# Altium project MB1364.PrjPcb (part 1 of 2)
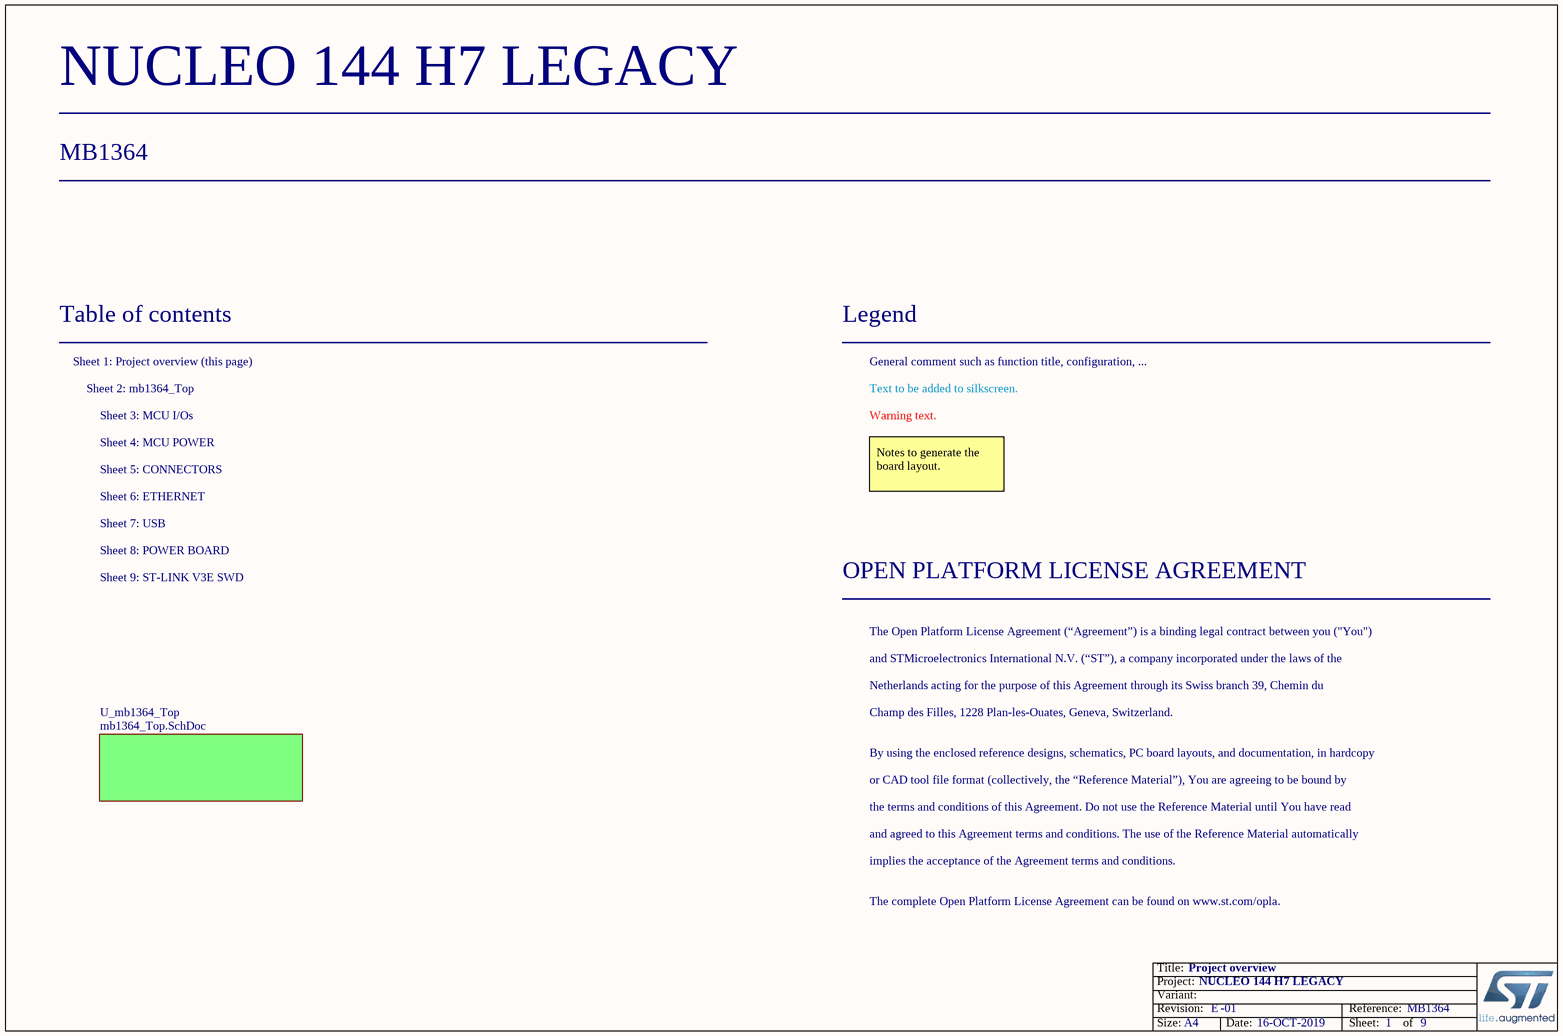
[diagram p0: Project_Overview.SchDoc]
Board_Reference: MB1364; Board_PCB_Revision: E; Board_Name: NUCLEO 144 H7 LEGACY; Board_Document_Date: 16-OCT-2019; Board_Assembly_Revision: 01
9 sheets, 324 parts. Net scope: flat (ports and power ports of the same name join across sheets).
Board file: MB1364.PcbDoc
Sheets:
  Project_Overview.SchDoc
    U_mb1364_Top = MB1364_Top.SchDoc
      U_Connectors = Connectors.SchDoc
      U_Power_Board = Power_Board.SchDoc
      U_MCU_144_IOs = MCU_144_IOs.SchDoc
      U_MCU_144_POWER = MCU_144_POWER.SchDoc
      U_USB = USB.SchDoc
      U_Ethernet = Ethernet.SchDoc
      U_ST_LINK_V3E = ST_LINK_V3E.SchDoc

## Sheet Project_Overview.SchDoc: Project overview
size A4; Date: Not used; ApprovedBy: Not used; CheckedBy: Not used; Author: Not used; CompanyName: STMicroelectronics; DrawnBy: Not used; Engineer: Not used; Organization: Not used; Address1: Not used; Address2: Not used; Address3: Not used; Address4: Not used; DocumentNumber: 1; Revision: Not used; SheetNumber: 1; SheetTotal: 9

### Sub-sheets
U_mb1364_Top = mb1364_Top.SchDoc: no entries

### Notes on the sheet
- Table of contents
- Sheet 1: Project overview (this page)
- Legend
- General comment such as function title, configuration, ...
- Sheet 2: mb1364_Top
- Sheet 4: MCU POWER
- Sheet 3: MCU I/Os
- Text to be added to silkscreen.
- Warning text.
- Sheet 6: ETHERNET
- Sheet 5: CONNECTORS
- Notes to generate the board layout.
- Sheet 9: ST-LINK V3E SWD
- Sheet 7: USB
- Sheet 8: POWER BOARD
- OPEN PLATFORM LICENSE AGREEMENT
- The Open Platform License Agreement (“Agreement”) is a binding legal contract between you ("You")
- and STMicroelectronics International N.V. (“ST”), a company incorporated under the laws of the
- Netherlands acting for the purpose of this Agreement through its Swiss branch 39, Chemin du
- Champ des Filles, 1228 Plan-les-Ouates, Geneva, Switzerland.
- By using the enclosed reference designs, schematics, PC board layouts, and documentation, in hardcopy
- or CAD tool file format (collectively, the “Reference Material”), You are agreeing to be bound by
- the terms and conditions of this Agreement. Do not use the Reference Material until You have read
- and agreed to this Agreement terms and conditions. The use of the Reference Material automatically
- implies the acceptance of the Agreement terms and conditions.
- The complete Open Platform License Agreement can be found on www.st.com/opla.

## Sheet MB1364_Top.SchDoc: MB1364 Top: hierarchical view
size A4; Date: Not used; ApprovedBy: Not used; CheckedBy: Not used; Author: Not used; CompanyName: STMicroelectronics; DrawnBy: Not used; Engineer: Not used; Organization: Not used; Address1: Not used; Address2: Not used; Address3: Not used; Address4: Not used; DocumentNumber: 2; Revision: Not used; SheetNumber: 2; SheetTotal: 9
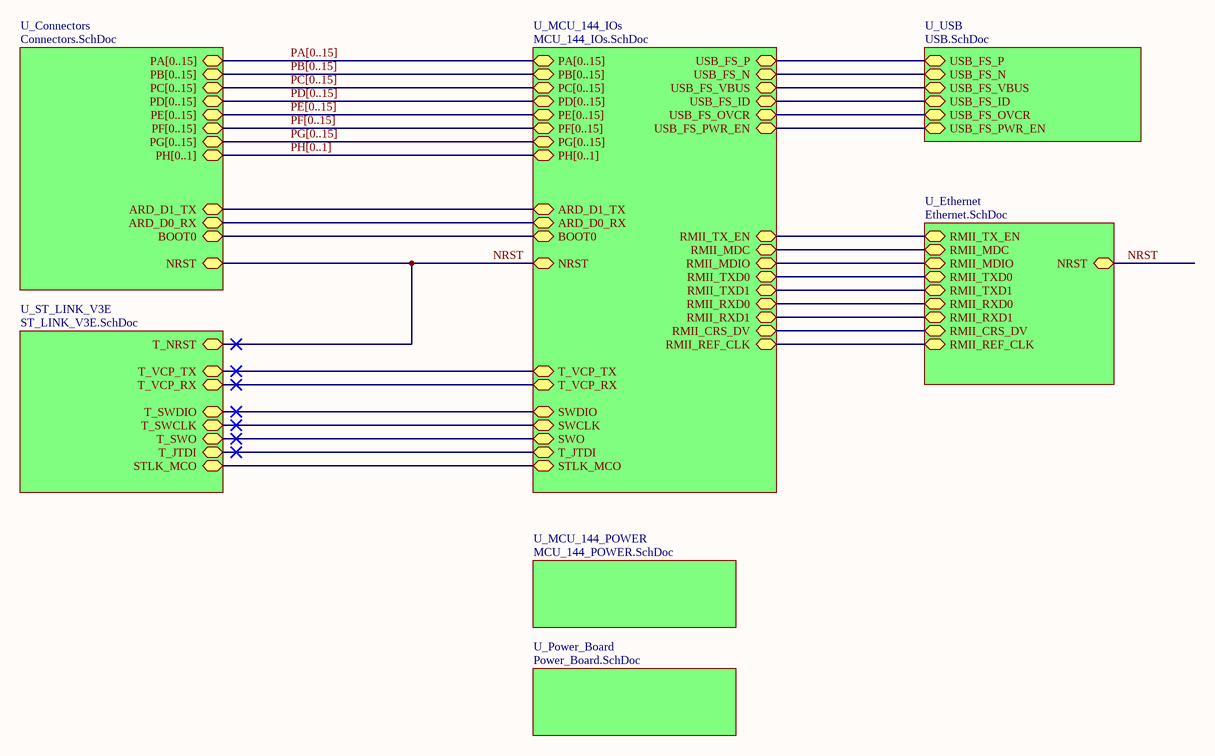
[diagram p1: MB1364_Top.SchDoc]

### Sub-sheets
U_Connectors = Connectors.SchDoc: PA[0..15] (bidir), PB[0..15] (bidir), PC[0..15] (bidir), PD[0..15] (bidir), PE[0..15] (bidir), PH[0..1] (bidir), ARD_D1_TX (bidir), ARD_D0_RX (bidir), NRST, BOOT0, PF[0..15] (bidir), PG[0..15] (bidir)
U_Ethernet = Ethernet.SchDoc: RMII_CRS_DV (bidir), RMII_REF_CLK (bidir), RMII_TXD0 (bidir), RMII_RXD0 (bidir), RMII_TX_EN (bidir), NRST (bidir), RMII_RXD1 (bidir), RMII_MDC (bidir), RMII_TXD1 (bidir), RMII_MDIO (bidir)
U_MCU_144_IOs = MCU_144_IOs.SchDoc: NRST (bidir), BOOT0 (bidir), SWO (bidir), STLK_MCO (bidir), SWCLK (bidir), SWDIO (bidir), RMII_TX_EN (bidir), RMII_MDC (bidir), RMII_TXD0 (bidir), RMII_TXD1 (bidir), RMII_REF_CLK (bidir), RMII_RXD1 (bidir), RMII_MDIO (bidir), RMII_CRS_DV (bidir), RMII_RXD0 (bidir), USB_FS_N (bidir), USB_FS_P (bidir), USB_FS_PWR_EN (bidir), USB_FS_VBUS (bidir), USB_FS_ID (bidir), T_VCP_TX (bidir), T_VCP_RX (bidir), PA[0..15] (bidir), PB[0..15] (bidir), PC[0..15] (bidir), PD[0..15] (bidir), PE[0..15] (bidir), PH[0..1] (bidir), ARD_D1_TX (bidir), ARD_D0_RX (bidir), USB_FS_OVCR, T_JTDI (bidir), PG[0..15] (bidir), PF[0..15] (bidir)
U_MCU_144_POWER = MCU_144_POWER.SchDoc: no entries
U_Power_Board = Power_Board.SchDoc: no entries
U_ST_LINK_V3E = ST_LINK_V3E.SchDoc: T_NRST (bidir), STLK_MCO (bidir), T_SWDIO (bidir), T_VCP_TX (bidir), T_VCP_RX (bidir), T_SWCLK (bidir), T_SWO (bidir), T_JTDI (bidir)
U_USB = USB.SchDoc: USB_FS_VBUS, USB_FS_N, USB_FS_P, USB_FS_ID, USB_FS_PWR_EN, USB_FS_OVCR

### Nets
NRST: sheet U_Connectors/NRST, sheet U_MCU_144_IOs/NRST, sheet U_Ethernet/NRST, sheet U_ST_LINK_V3E/T_NRST
(unnamed): sheet U_Connectors/ARD_D1_TX, sheet U_MCU_144_IOs/ARD_D1_TX
(unnamed): sheet U_Connectors/ARD_D0_RX, sheet U_MCU_144_IOs/ARD_D0_RX  [a separate net that carries the same name]
(unnamed): sheet U_Connectors/BOOT0, sheet U_MCU_144_IOs/BOOT0  [a separate net that carries the same name]
(unnamed): sheet U_MCU_144_IOs/SWO, sheet U_ST_LINK_V3E/T_SWO  [a separate net that carries the same name]
(unnamed): sheet U_MCU_144_IOs/STLK_MCO, sheet U_ST_LINK_V3E/STLK_MCO  [a separate net that carries the same name]
(unnamed): sheet U_MCU_144_IOs/SWCLK, sheet U_ST_LINK_V3E/T_SWCLK  [a separate net that carries the same name]
(unnamed): sheet U_MCU_144_IOs/SWDIO, sheet U_ST_LINK_V3E/T_SWDIO  [a separate net that carries the same name]
(unnamed): sheet U_MCU_144_IOs/RMII_TX_EN, sheet U_Ethernet/RMII_TX_EN  [a separate net that carries the same name]
(unnamed): sheet U_MCU_144_IOs/RMII_MDC, sheet U_Ethernet/RMII_MDC  [a separate net that carries the same name]
(unnamed): sheet U_MCU_144_IOs/RMII_TXD0, sheet U_Ethernet/RMII_TXD0  [a separate net that carries the same name]
(unnamed): sheet U_MCU_144_IOs/RMII_TXD1, sheet U_Ethernet/RMII_TXD1  [a separate net that carries the same name]
(unnamed): sheet U_MCU_144_IOs/RMII_REF_CLK, sheet U_Ethernet/RMII_REF_CLK  [a separate net that carries the same name]
(unnamed): sheet U_MCU_144_IOs/RMII_RXD1, sheet U_Ethernet/RMII_RXD1  [a separate net that carries the same name]
(unnamed): sheet U_MCU_144_IOs/RMII_MDIO, sheet U_Ethernet/RMII_MDIO  [a separate net that carries the same name]
(unnamed): sheet U_MCU_144_IOs/RMII_CRS_DV, sheet U_Ethernet/RMII_CRS_DV  [a separate net that carries the same name]
(unnamed): sheet U_MCU_144_IOs/RMII_RXD0, sheet U_Ethernet/RMII_RXD0  [a separate net that carries the same name]
(unnamed): sheet U_MCU_144_IOs/USB_FS_N, sheet U_USB/USB_FS_N  [a separate net that carries the same name]
(unnamed): sheet U_MCU_144_IOs/USB_FS_P, sheet U_USB/USB_FS_P  [a separate net that carries the same name]
(unnamed): sheet U_MCU_144_IOs/USB_FS_PWR_EN, sheet U_USB/USB_FS_PWR_EN  [a separate net that carries the same name]
(unnamed): sheet U_MCU_144_IOs/USB_FS_VBUS, sheet U_USB/USB_FS_VBUS  [a separate net that carries the same name]
(unnamed): sheet U_MCU_144_IOs/USB_FS_ID, sheet U_USB/USB_FS_ID  [a separate net that carries the same name]
(unnamed): sheet U_MCU_144_IOs/T_VCP_TX, sheet U_ST_LINK_V3E/T_VCP_TX  [a separate net that carries the same name]
(unnamed): sheet U_MCU_144_IOs/T_VCP_RX, sheet U_ST_LINK_V3E/T_VCP_RX  [a separate net that carries the same name]
(unnamed): sheet U_MCU_144_IOs/USB_FS_OVCR, sheet U_USB/USB_FS_OVCR  [a separate net that carries the same name]
(unnamed): sheet U_MCU_144_IOs/T_JTDI, sheet U_ST_LINK_V3E/T_JTDI  [a separate net that carries the same name]

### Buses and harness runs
bus PA[0..15] = sheet U_Connectors/PA[0..15] = sheet U_MCU_144_IOs/PA[0..15]
bus PB[0..15] = sheet U_Connectors/PB[0..15] = sheet U_MCU_144_IOs/PB[0..15]
bus PC[0..15] = sheet U_Connectors/PC[0..15] = sheet U_MCU_144_IOs/PC[0..15]
bus PD[0..15] = sheet U_Connectors/PD[0..15] = sheet U_MCU_144_IOs/PD[0..15]
bus PE[0..15] = sheet U_Connectors/PE[0..15] = sheet U_MCU_144_IOs/PE[0..15]
bus PF[0..15] = sheet U_Connectors/PF[0..15] = sheet U_MCU_144_IOs/PF[0..15]
bus PG[0..15] = sheet U_Connectors/PG[0..15] = sheet U_MCU_144_IOs/PG[0..15]
bus PH[0..1] = sheet U_Connectors/PH[0..1] = sheet U_MCU_144_IOs/PH[0..1]

## Sheet Connectors.SchDoc: Connectors
size A3; Date: Not used; ApprovedBy: Not used; CheckedBy: Not used; Author: Not used; CompanyName: STMicroelectronics; DrawnBy: Not used; Engineer: Not used; Organization: Not used; Address1: Not used; Address2: Not used; Address3: Not used; Address4: Not used; DocumentNumber: 5; Revision: Not used; SheetNumber: 5; SheetTotal: 9
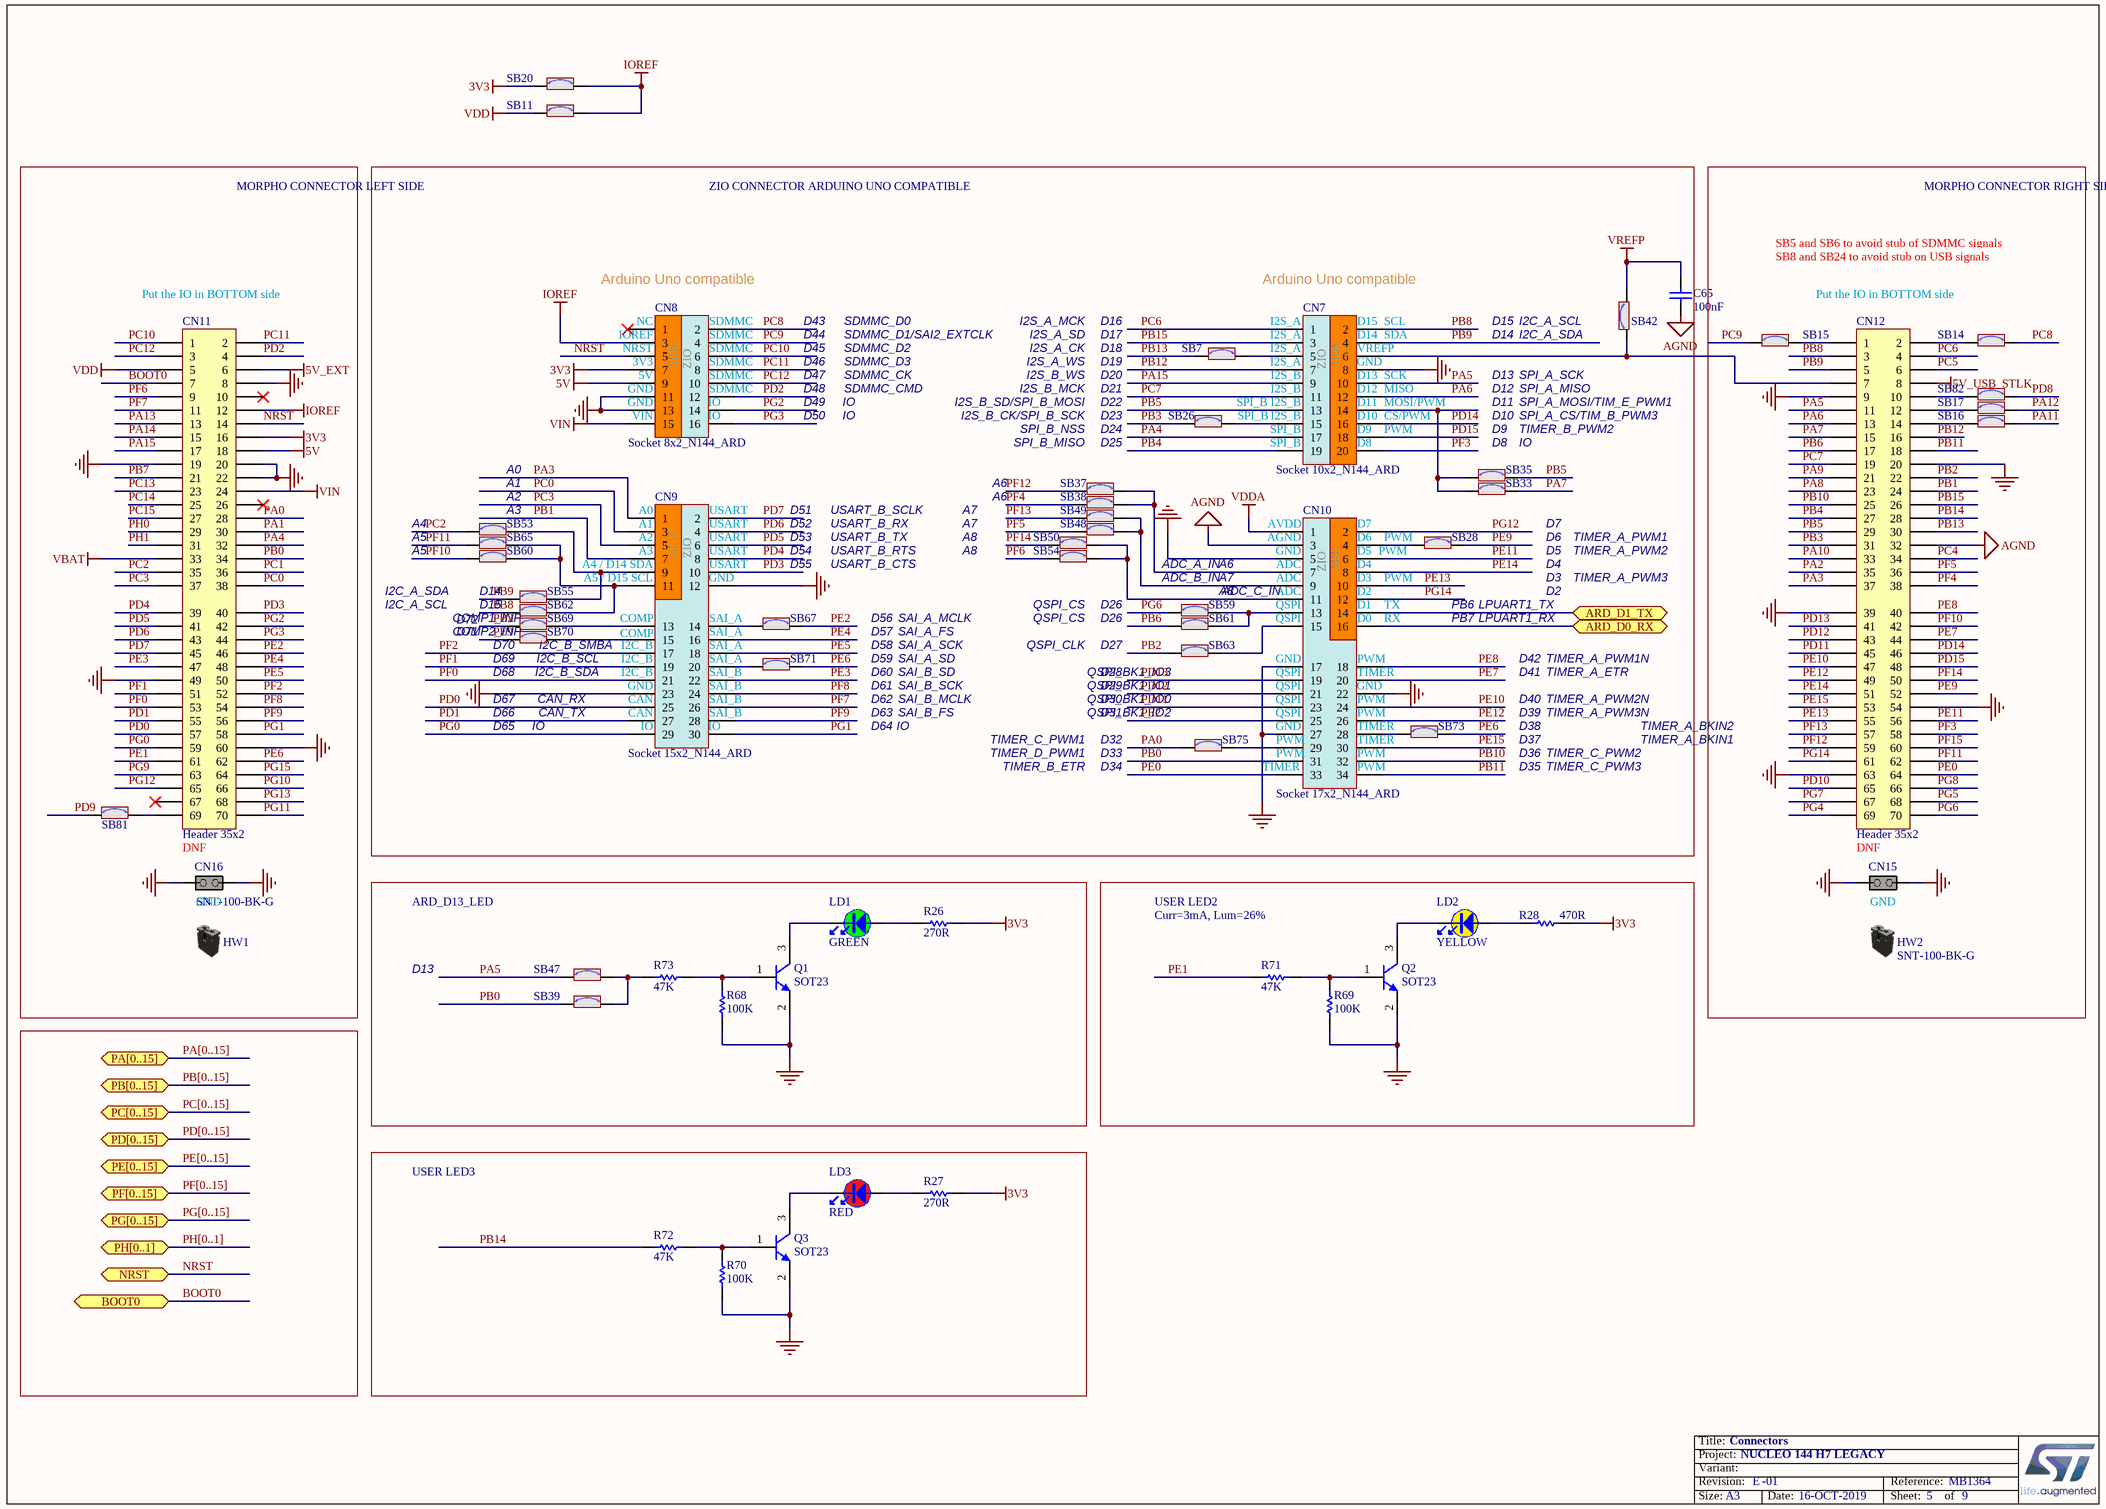
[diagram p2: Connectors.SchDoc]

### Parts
C65  value 100nF  [C0603]  (hidden comment: Capacitor)
CN7  Socket 10x2_N144_ARD  [CON_SAMTEC_SSW-110-23-X-D_N144_ARD]
CN8  Socket 8x2_N144_ARD  [CON_SAMTEC_SSW-108-23-X-D_N144_ARD]
CN9  Socket 15x2_N144_ARD  [CON_SAMTEC_SSW-115-23-X-D_N144_ARD]
CN10  Socket 17x2_N144_ARD  [CON_SAMTEC_SSW-117-23-X-D_N144_ARD]
CN11  Header 35x2  [CON_SAMTEC_TSW-135-07-X-D]
CN12  Header 35x2  [CON_SAMTEC_TSW-135-07-X-D]
CN15  Jumper_Header 2x1  [CON_SAMTEC_TSW-102-09-X-S]  (value not drawn)
CN16  Jumper_Header 2x1  [CON_SAMTEC_TSW-102-09-X-S]  (value not drawn)
HW1  value SNT-100-BK-G  (hidden comment: Shunt Black 2.54mm)  (mechanical)
HW2  value SNT-100-BK-G  (hidden comment: Shunt Black 2.54mm)  (mechanical)
LD1  value GREEN  [LED_0603_OSRAM_LG-Q396-PS-35_GREEN_1A2K_H0P4]  (hidden comment: LED_green)
LD2  value YELLOW  [LED_0603_OSRAM_LY-Q396-P1Q2-36_YELLOW_1A2K_H0P4]  (hidden comment: LED_yellow)
LD3  value RED  [LED_0603_OSRAM_LS-Q976-NR-1_RED_1A2K_H0P8]  (hidden comment: LED_red)
Q1  value SOT23  [NPN_SOT23]  (hidden comment: 9013-SOT23)
Q2  value SOT23  [NPN_SOT23]  (hidden comment: 9013-SOT23)
Q3  value SOT23  [NPN_SOT23]  (hidden comment: 9013-SOT23)
R26  value 270R  [R0402]  (hidden comment: Resistor)
R27  value 270R  [R0402]  (hidden comment: Resistor)
R28  value 470R  [R0402]  (hidden comment: Resistor)
R68  value 100K  [R0603]  (hidden comment: Resistor)
R69  value 100K  [R0603]  (hidden comment: Resistor)
R70  value 100K  [R0603]  (hidden comment: Resistor)
R71  value 47K  [R0603]  (hidden comment: Resistor)
R72  value 47K  [R0603]  (hidden comment: Resistor)
R73  value 47K  [R0603]  (hidden comment: Resistor)
SB7  SB_ON  [SOLDER-BRIDGE_R0603-0R]  (value not drawn)
SB11  SB_ON  [SOLDER-BRIDGE_R0603-0R]  (value not drawn)
SB14  SB_ON  [SOLDER-BRIDGE_R0603-0R]  (value not drawn)
SB15  SB_ON  [SOLDER-BRIDGE_R0603-0R]  (value not drawn)
SB16  SB_ON  [SOLDER-BRIDGE_R0603-0R]  (value not drawn)
SB17  SB_ON  [SOLDER-BRIDGE_R0603-0R]  (value not drawn)
SB20  SB_ON  [SOLDER-BRIDGE_R0603-0R]  (value not drawn)
SB26  SB_ON  [SOLDER-BRIDGE_R0603-0R]  (value not drawn)
SB28  SB_ON  [SOLDER-BRIDGE_R0402-0R]  (value not drawn)
SB33  SB_ON  [SOLDER-BRIDGE_R0603-0R]  (value not drawn)
SB35  SB_ON  [SOLDER-BRIDGE_R0603-0R]  (value not drawn)
SB37  SB_ON  [SOLDER-BRIDGE_R0402-0R]  (value not drawn)
SB38  SB_ON  [SOLDER-BRIDGE_R0402-0R]  (value not drawn)
SB39  SB_ON  [SOLDER-BRIDGE_R0603-0R]  (value not drawn)
SB42  SB_ON  [SOLDER-BRIDGE_R0603-0R]  (value not drawn)
SB47  SB_ON  [SOLDER-BRIDGE_R0603-0R]  (value not drawn)
SB48  SB_ON  [SOLDER-BRIDGE_R0402-0R]  (value not drawn)
SB49  SB_ON  [SOLDER-BRIDGE_R0402-0R]  (value not drawn)
SB50  SB_ON  [SOLDER-BRIDGE_R0402-0R]  (value not drawn)
SB53  SB_ON  [SOLDER-BRIDGE_R0402-0R]  (value not drawn)
SB54  SB_ON  [SOLDER-BRIDGE_R0402-0R]  (value not drawn)
SB55  SB_ON  [SOLDER-BRIDGE_R0402-0R]  (value not drawn)
SB59  SB_ON  [SOLDER-BRIDGE_R0402-0R]  (value not drawn)
SB60  SB_ON  [SOLDER-BRIDGE_R0402-0R]  (value not drawn)
SB61  SB_ON  [SOLDER-BRIDGE_R0402-0R]  (value not drawn)
SB62  SB_ON  [SOLDER-BRIDGE_R0402-0R]  (value not drawn)
SB63  SB_ON  [SOLDER-BRIDGE_R0402-0R]  (value not drawn)
SB65  SB_ON  [SOLDER-BRIDGE_R0402-0R]  (value not drawn)
SB67  SB_ON  [SOLDER-BRIDGE_R0402-0R]  (value not drawn)
SB69  SB_ON  [SOLDER-BRIDGE_R0402-0R]  (value not drawn)
SB70  SB_ON  [SOLDER-BRIDGE_R0402-0R]  (value not drawn)
SB71  SB_ON  [SOLDER-BRIDGE_R0402-0R]  (value not drawn)
SB73  SB_ON  [SOLDER-BRIDGE_R0402-0R]  (value not drawn)
SB75  SB_ON  [SOLDER-BRIDGE_R0402-0R]  (value not drawn)
SB81  SB_ON  [SOLDER-BRIDGE_R0402-0R]  (value not drawn)
SB82  SB_ON  [SOLDER-BRIDGE_R0402-0R]  (value not drawn)

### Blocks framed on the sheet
USER LED3: LD3 Q3 R27 R70 R72

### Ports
ARD_D0_RX (bidir), ARD_D1_TX (bidir), BOOT0, NRST, PA[0..15] (bidir), PB[0..15] (bidir), PC[0..15] (bidir), PD[0..15] (bidir), PE[0..15] (bidir), PF[0..15] (bidir), PG[0..15] (bidir), PH[0..1] (bidir)

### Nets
3V3: CN8.7 CN11.16 R26.2 R27.2 R28.2 SB20.1
5V: CN8.9 CN11.18
5V_EXT: CN11.6
5V_USB_STLK: CN12.8
AGND: C65.1 CN10.3 CN12.32
GND: CN7.8 CN8.11 CN8.13 CN9.12 CN9.23 CN10.5 CN10.17 CN10.22 CN10.27 CN11.8 CN11.19 CN11.20 CN11.22 CN11.49 CN11.60 CN12.9 CN12.20 CN12.39 CN12.54 CN12.63 CN15.1(COMMON) CN15.2(NO) CN16.1(COMMON) CN16.2(NO) Q1.2(E) Q2.2(E) Q3.2(E) R68.1 R69.1 R70.1
IOREF: CN8.3 CN11.12 SB11.2 SB20.2
VBAT: CN11.33
VDD: CN11.5 SB11.1
VDDA: CN10.1
VIN: CN8.15 CN11.24
VREFP: C65.2 SB42.2
ARD_D0_RX: CN10.16 ; port ARD_D0_RX
ARD_D1_TX: CN10.14 ; port ARD_D1_TX
BOOT0: CN11.7 ; port BOOT0
NRST: CN8.5 CN11.14 ; port NRST
PA0: CN11.28 SB75.1
PA1: CN11.30
PA2: CN12.35
PA3: CN9.1 CN12.37
PA4: CN7.17 CN11.32
PA5: CN7.10 CN12.11 SB47.1
PA6: CN7.12 CN12.13
PA7: CN12.15 SB33.2
PA8: CN12.23
PA9: CN12.21
PA10: CN12.33
PA11: SB16.2
PA12: SB17.2
PA13: CN11.13
PA14: CN11.15
PA15: CN7.9 CN11.17
PB0: CN10.31 CN11.34 SB39.1
PB1: CN9.7 CN12.24
PB2: CN12.22 SB63.1 SB69.1
PB3: CN12.31 SB26.1
PB4: CN7.19 CN12.27
PB5: CN7.13 CN12.29 SB35.2
PB6: CN12.17 SB61.1
PB7: CN11.21
PB8: CN7.2 CN12.3 SB62.1
PB9: CN7.4 CN12.5 SB55.1
PB10: CN10.32 CN12.25
PB11: CN10.34 CN12.18
PB12: CN7.7 CN12.16
PB13: CN12.30 SB7.1
PB14: CN12.28 R72.1
PB15: CN7.3 CN12.26
PC0: CN9.3 CN11.38
PC1: CN11.36
PC2: CN11.35 SB53.1
PC3: CN9.5 CN11.37
PC4: CN12.34
PC5: CN12.6
PC6: CN7.1 CN12.4
PC7: CN7.11 CN12.19
PC8: CN8.2 SB14.2
PC9: CN8.4 SB15.1
PC10: CN8.6 CN11.1
PC11: CN8.8 CN11.2
PC12: CN8.10 CN11.3
PC13: CN11.23
PC14: CN11.25
PC15: CN11.27
PD0: CN9.25 CN11.57
PD1: CN9.27 CN11.55
PD2: CN8.12 CN11.4
PD3: CN9.10 CN11.40
PD4: CN9.8 CN11.39
PD5: CN9.6 CN11.41
PD6: CN9.4 CN11.43
PD7: CN9.2 CN11.45
PD8: SB82.2
PD9: SB81.1
PD10: CN12.65
PD11: CN10.23 CN12.45
PD12: CN10.21 CN12.43
PD13: CN10.19 CN12.41
PD14: CN7.16 CN12.46
PD15: CN7.18 CN12.48
PE0: CN10.33 CN12.64
PE1: CN11.61 R71.1
PE2: CN10.25 CN11.46 SB67.2
PE3: CN9.22 CN11.47
PE4: CN9.16 CN11.48
PE5: CN9.18 CN11.50
PE6: CN11.62 SB71.2 SB73.2
PE7: CN10.20 CN12.44
PE8: CN10.18 CN12.40
PE9: CN12.52 SB28.2 SB70.1
PE10: CN10.24 CN12.47
PE11: CN10.6 CN12.56
PE12: CN10.26 CN12.49
PE13: CN10.10 CN12.55
PE14: CN10.8 CN12.51
PE15: CN10.30 CN12.53
PF0: CN9.21 CN11.53
PF1: CN9.19 CN11.51
PF2: CN9.17 CN11.52
PF3: CN7.20 CN12.58
PF4: CN12.38 SB38.1
PF5: CN12.36 SB48.1
PF6: CN11.9 SB54.1
PF7: CN9.26 CN11.11
PF8: CN9.24 CN11.54
PF9: CN9.28 CN11.56
PF10: CN12.42 SB60.1
PF11: CN12.62 SB65.1
PF12: CN12.59 SB37.1
PF13: CN12.57 SB49.1
PF14: CN12.50 SB50.1
PF15: CN12.60
PG0: CN9.29 CN11.59
PG1: CN9.30 CN11.58
PG2: CN8.14 CN11.42
PG3: CN8.16 CN11.44
PG4: CN12.69
PG5: CN12.68
PG6: CN12.70 SB59.1
PG7: CN12.67
PG8: CN12.66
PG9: CN11.63
PG10: CN11.66
PG11: CN11.70
PG12: CN10.2 CN11.65
PG13: CN11.68
PG14: CN10.12 CN12.61
PG15: CN11.64
PH0: CN11.29
PH1: CN11.31
NetCN7_5: CN7.5 SB7.2
NetCN7_6: CN7.6 CN12.7 SB42.1
NetCN7_14: CN7.14 SB33.1 SB35.1
NetCN7_15: CN7.15 SB26.2
NetCN9_9: CN9.9 SB53.2 SB55.2
NetCN9_11: CN9.11 SB60.2 SB62.2 SB65.2
NetCN9_13: CN9.13 SB69.2
NetCN9_14: CN9.14 SB67.1
NetCN9_15: CN9.15 SB70.2
NetCN9_20: CN9.20 SB71.1
NetCN10_4: CN10.4 SB28.1
NetCN10_7: CN10.7 SB37.2 SB38.2
NetCN10_9: CN10.9 SB48.2 SB49.2
NetCN10_11: CN10.11 SB50.2 SB54.2
NetCN10_13: CN10.13 SB59.2 SB61.2
NetCN10_15: CN10.15 SB63.2
NetCN10_28: CN10.28 SB73.1
NetCN10_29: CN10.29 SB75.2
NetCN11_69: CN11.69 SB81.2
NetCN12_1: CN12.1 SB15.2
NetCN12_2: CN12.2 SB14.1
NetCN12_10: CN12.10 SB82.1
NetCN12_12: CN12.12 SB17.1
NetCN12_14: CN12.14 SB16.1
NetLD1_1: LD1.1 R26.1
NetLD1_2: LD1.2 Q1.3(C)
NetLD2_1: LD2.1 R28.1
NetLD2_2: LD2.2 Q2.3(C)
NetLD3_1: LD3.1 R27.1
NetLD3_2: LD3.2 Q3.3(C)
NetQ1_1: Q1.1(B) R68.2 R73.2
NetQ2_1: Q2.1(B) R69.2 R71.2
NetQ3_1: Q3.1(B) R70.2 R72.2
NetR73_1: R73.1 SB39.2 SB47.2

Not connected (* = marked no-connect by the designer): CN8 1*; CN11 10* 26* 67*

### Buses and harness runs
bus PA[0..15] = port PA[0..15]
bus PB[0..15] = port PB[0..15]
bus PC[0..15] = port PC[0..15]
bus PD[0..15] = port PD[0..15]
bus PE[0..15] = port PE[0..15]
bus PF[0..15] = port PF[0..15]
bus PG[0..15] = port PG[0..15]
bus PH[0..1] = port PH[0..1]

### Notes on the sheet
- MORPHO CONNECTOR LEFT SIDE
- ZIO CONNECTOR ARDUINO UNO COMPATIBLE
- MORPHO CONNECTOR RIGHT SIDE
- (near CN11) Put the IO in BOTTOM side
- (near CN8) Arduino Uno compatible
- (near CN7) Arduino Uno compatible
- SB5 and SB6 to avoid stub of SDMMC signals
- SB8 and SB24 to avoid stub on USB signals
- Put the IO in BOTTOM side
- (near CN8) NC
- (near CN8) IOREF
- (near CN8) NRST
- (near CN8) 3V3
- (near CN8) 5V
- (near CN8) SDMMC
- D43
- D44
- D45
- D46
- D47
- SDMMC_CK
- SDMMC_D0
- SDMMC_D1/SAI2_EXTCLK
- SDMMC_D2
- SDMMC_D3
- I2S_A_SD
- I2S_A_CK
- I2S_A_WS
- I2S_A_MCK
- I2S_B_WS
- D16
- D17
- D18
- D19
- D20
- (near CN7) I2S_A
- (near CN7) I2S_B
- (near CN7) VREFP
- (near CN7) D13
- (near CN7) D14
- (near CN7) D15
- (near CN7) SCL
- (near CN7) SDA
- (near CN7) SCK
- (near CN7) GND
- D15
- D14
- D13
- SPI_A_SCK
- (near SB42) I2C_A_SCL
- (near SB42) I2C_A_SDA
- (near CN8) GND
- (near CN8) VIN
- (near CN8) IO
- D48
- D49
- D50
- SDMMC_CMD
- IO
- I2S_B_SD/SPI_B_MOSI
- I2S_B_CK/SPI_B_SCK
- I2S_B_MCK
- SPI_B_MISO
- SPI_B_NSS
- D21
- D22
- D23
- D24
- D25
- SPI_B
- (near SB26) SPI_B
- (near CN7) SPI_B
- (near CN7) D8
- (near CN7) D9
- (near CN7) D10
- (near CN7) D11
- (near CN7) D12
- (near CN7) MISO
- (near CN7) MOSI/PWM
- (near CN7) CS/PWM
- (near CN7) PWM
- D12
- D11
- D10
- D9
- D8
- TIMER_B_PWM2
- SPI_A_CS/TIM_B_PWM3
- SPI_A_MOSI/TIM_E_PWM1
- SPI_A_MISO
- A0
- A1
- A2
- (near SB53) A3
- (near CN9) A0
- (near CN9) USART
- D51
- USART_B_SCLK
- A7
- A6
- A4
- A5
- (near CN9) A1
- (near CN9) A2
- (near CN9) A3
- (near CN9) A4 / D14 SDA
- (near CN9) A5 / D15 SCL
- (near CN9) GND
- D52
- D53
- D54
- D55
- USART_B_TX
- USART_B_RX
- USART_B_CTS
- USART_B_RTS
- A8
- ADC_A_IN
- ADC_B_IN
- (near CN10) GND
- (near CN10) AVDD
- (near CN10) AGND
- (near CN10) ADC
- (near CN10) D7
- (near CN10) D6
- (near CN10) D5
- (near CN10) D4
- (near CN10) D3
- PWM
- D5
- D6
- D7
- D4
- D3
- TIMER_A_PWM1
- TIMER_A_PWM2
- TIMER_A_PWM3
- I2C_A_SCL
- I2C_A_SDA
- COMP1_INP
- COMP2_INP
- D72
- D71
- D70
- (near SB70) I2C_B_SMBA
- (near CN9) COMP
- (near CN9) I2C_B
- (near CN9) SAI_A
- D56
- D57
- D58
- SAI_A_SCK
- SAI_A_FS
- SAI_A_MCLK
- QSPI_CLK
- QSPI_CS
- D26
- D27
- (near SB59) ADC_C_IN
- (near CN10) QSPI
- (near CN10) D2
- (near CN10) D1
- (near CN10) D0
- (near CN10) TX
- (near CN10) RX
- PB6
- PB7
- LPUART1_TX
- LPUART1_RX
- D2
- (near SB70) D69
- D68
- D67
- D66
- CAN_TX
- CAN_RX
- (near SB70) I2C_B_SCL
- I2C_B_SDA
- (near CN9) CAN
- (near CN9) SAI_B
- D59
- D60
- D61
- D62
- D63
- SAI_A_SD
- SAI_B_SD
- SAI_B_SCK
- SAI_B_FS
- SAI_B_MCLK
- QSPI_BK1_IO0
- QSPI_BK1_IO2
- QSPI_BK1_IO1
- QSPI_BK1_IO3
- D28
- D29
- D30
- D31
- (near CN10) TIMER
- (near CN10) PWM
- D39
- D40
- D41
- D42
- TIMER_A_PWM1N
- TIMER_A_PWM2N
- TIMER_A_PWM3N
- TIMER_A_ETR
- D65
- (near CN9) IO
- D64
- TIMER_D_PWM1
- TIMER_B_ETR
- TIMER_C_PWM1
- D32
- D33
- D34
- D35
- D36
- D37
- D38
- TIMER_C_PWM2
- TIMER_C_PWM3
- TIMER_A_BKIN1
- TIMER_A_BKIN2
- DNF
- GND
- ARD_D13_LED
- USER LED2
- Curr=3mA, Lum=26%

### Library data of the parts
C65 = MCD-00237: Capacitor, MLCC, 100nF, 6V3, X5R, 10%, 0603, T=0,8mm; Manufacturer_Part_Number: CC0603KRX5R5BB104; Manufacturer: YAGEO; Provided_By: SUBCO; ECCN_US: EAR99; ECCN_EU: NEC
CN7 = MCD-01039: Socket, 10x2, 2.54mm, VR, TH, Height 8.51mm/10mm, Low insertion force.; Part_Type: Connector; Manufacturer_Part_Number: SSW-110-23-x-D; Manufacturer: SAMTEC; Provided_By: SUBCO
CN8 = MCD-01037: Socket, 8x2, 2.54mm, VR, TH, Height 8.51mm/10mm, Low insertion force.; Part_Type: Connector; Manufacturer_Part_Number: SSW-108-23-x-D; Manufacturer: SAMTEC; Provided_By: SUBCO
CN9 = MCD-01040: Socket, 15x2, 2.54mm, VR, TH, Height 8.51mm/10mm, Low insertion force.; Part_Type: Connector; Manufacturer_Part_Number: SSW-115-23-x-D; Manufacturer: SAMTEC; Provided_By: SUBCO
CN10 = MCD-01041: Socket, 17x2, 2.54mm, VR, TH, Height 8.51mm/10mm, Low insertion force; Part_Type: Connector; Manufacturer_Part_Number: SSW-117-23-x-D; Manufacturer: SAMTEC; Provided_By: SUBCO
CN11 CN12 = MCD-01210: Header, 35x2, 2,54mm, VR, TH, Height 5.84mm/2.54mm; Part_Type: Connector; Manufacturer_Part_Number: TSW-135-07-x-D; Manufacturer: SAMTEC; Provided_By: SUBCO
CN15 CN16 = MCD-00214: Header, 2x1, 2,54mm, VR, TH, Height 5.84mm/10.16mm; Manufacturer_Part_Number: TSW-102-09-x-S; Manufacturer: SAMTEC; Part_Type: Connector; Value: Header 2x1 16mm; Provided_By: SUBCO
HW1 HW2 = MCD-00043: SHUNT 2.54mm BLACK; Manufacturer: SAMTEC; Part_Type: Mechanical; Alternate_Manufacturer_Part_Number: 316102S111A; Alternate_Manufacturer: JIUBABA; Provided_By: SUBCO
LD1 = MCD-00588: LED Green, 0603 SMD, Forward Voltage Typ=2V, Max=2.5V; Part_Type: Display; Manufacturer_Part_Number: LG Q396-PS-35; Manufacturer: OSRAM OPTO SEMICONDUCTORS; Alternate_Manufacturer_Part_Number: VLMTG1300-GS08; Alternate_Manufacturer: VISHAY SEMICONDUCTOR OPTO DIVISION; Provided_By: SUBCO
LD2 = MCD-01061: LED Yellow, 0603 SMD, Forward Voltage min=1.7V, Typ=2V, Max=2.3V; Part_Type: Display; Manufacturer_Part_Number: LY Q396-P1Q2-36; Manufacturer: OSRAM OPTO SEMICONDUCTORS; Provided_By: SUBCO
LD3 = MCD-00586: LED Red, 0603 SMD, Forward Voltage Typ=2V, Max=2.5V; Part_Type: Display; Manufacturer_Part_Number: LS Q976-NR-1; Manufacturer: OSRAM OPTO SEMICONDUCTORS; Alternate_Manufacturer_Part_Number: VLMS1300-GS08; Alternate_Manufacturer: VISHAY SEMICONDUCTOR OPTO DIVISION; Provided_By: SUBCO
Q1-Q3 = MCD-00073: NPN Bipolar Transistor; Part_Type: IC; Manufacturer_Part_Number: BSR14; Manufacturer: ON SEMICONDUCTOR; Alternate_Manufacturer_Part_Number: MMBT2222ALT1G / MMBT2222ALT3G; Provided_By: SUBCO; ECCN_US: EAR99; ECCN_EU: NEC
R26 R27 = MCD-00441: Resistor,270R,0402,1%,1/16W; Manufacturer_Part_Number: RC0402FR-07270RL; Manufacturer: YAGEO; Provided_By: SUBCO; ECCN_US: EAR99; ECCN_EU: NEC
R28 = MCD-00178: Resistor,470R,0402,1%,1/16W; Manufacturer_Part_Number: RC0402FR-07470RL; Manufacturer: YAGEO; Provided_By: SUBCO; ECCN_US: EAR99; ECCN_EU: NEC
R68-R70 = MCD-00223: Resistor,100K,0603,1%,1/10W; Manufacturer_Part_Number: RC0603FR-07100KL; Manufacturer: YAGEO; Provided_By: SUBCO; ECCN_US: EAR99; ECCN_EU: NEC
R71-R73 = MCD-00222: Resistor,47K,0603,1%,1/10W; Manufacturer_Part_Number: RC0603FR-0747KL; Manufacturer: YAGEO; Provided_By: SUBCO; ECCN_US: EAR99; ECCN_EU: NEC
SB7 SB11 SB14-SB17 SB20 SB26 SB33 SB35 SB39 SB42 SB47 = MCD-00071: Solder Bridge ON; Part_Type: Mechanical; Manufacturer_Part_Number: RC0603JR-070RL; Manufacturer: YAGEO; Provided_By: SUBCO
SB28 SB37 SB38 SB48-SB50 SB53-SB55 SB59-SB63 SB65 SB67 SB69-SB71 SB73 SB75 SB81 SB82 = MCD-01618: Solder Bridge 0402 ON; Part_Type: Mechanical; Manufacturer_Part_Number: RC0402JR-070RL; Manufacturer: YAGEO; Provided_By: SUBCO

## Sheet Power_Board.SchDoc: MAIN POWER 5V / 3V3 / 1V8
size A4; Date: Not used; ApprovedBy: Not used; CheckedBy: Not used; Author: Not used; CompanyName: STMicroelectronics; DrawnBy: Not used; Engineer: Not used; Organization: Not used; Address1: Not used; Address2: Not used; Address3: Not used; Address4: Not used; DocumentNumber: 9; Revision: Not used; SheetNumber: 8; SheetTotal: 9
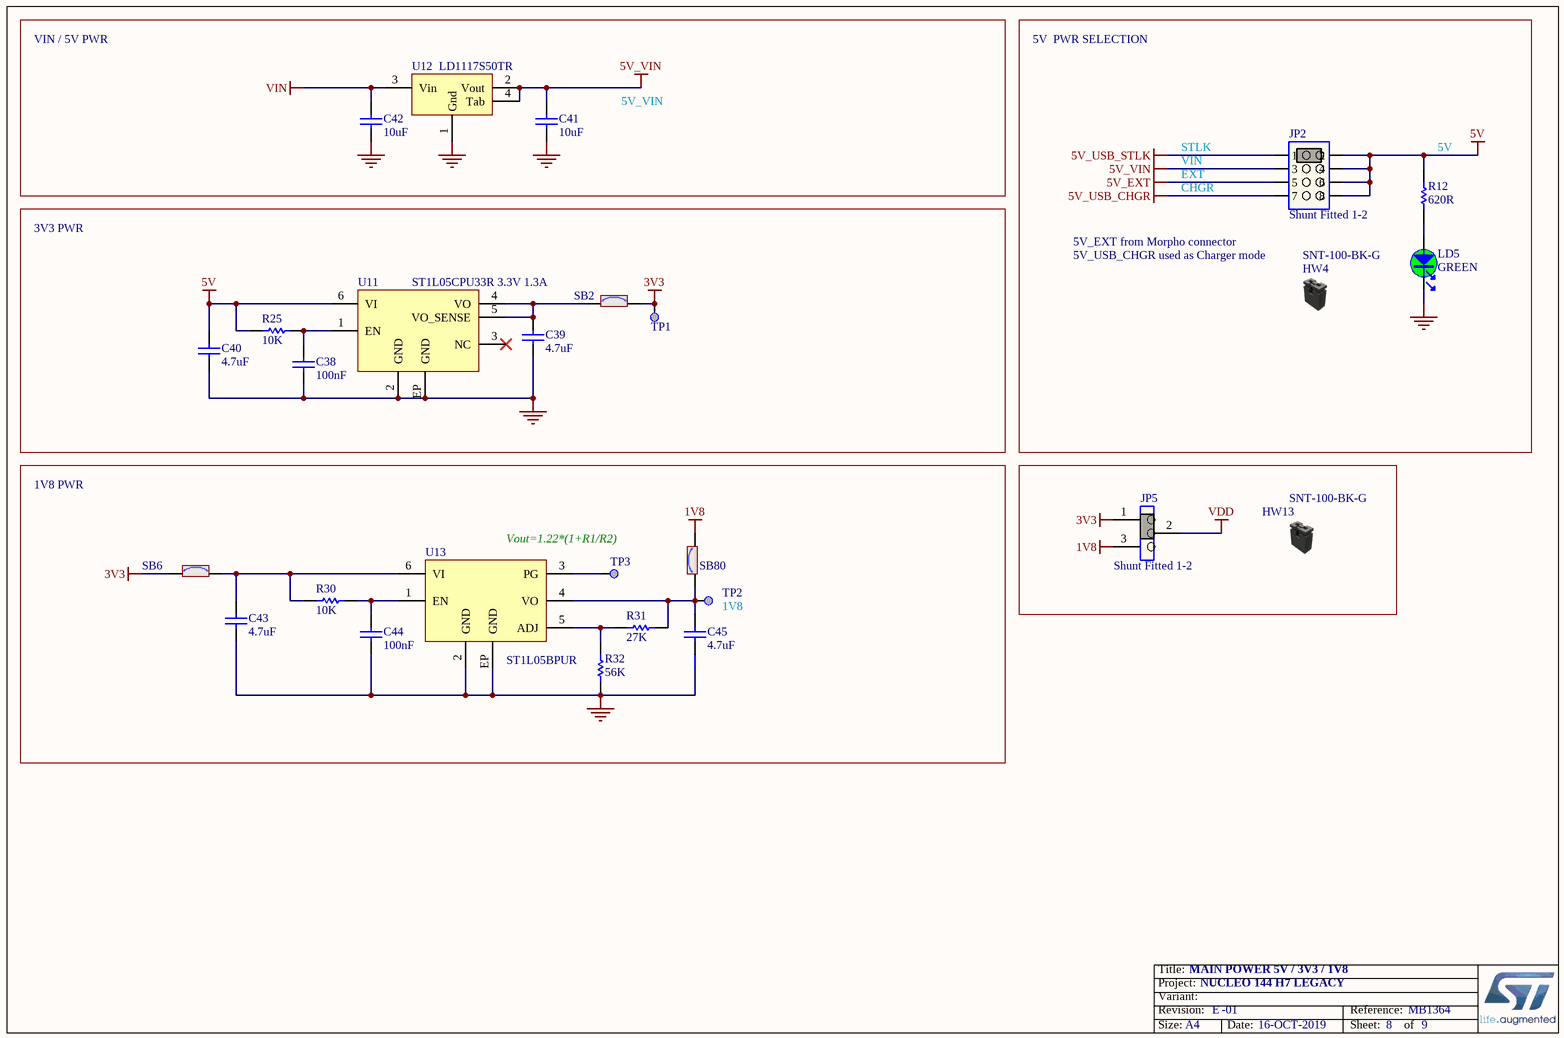
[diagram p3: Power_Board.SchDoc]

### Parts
C38  value 100nF  [C0402]  (hidden comment: Capacitor)
C39  value 4.7uF  [C0603]  (hidden comment: Capacitor)
C40  value 4.7uF  [C0603]  (hidden comment: Capacitor)
C41  value 10uF  [C0805]  (hidden comment: Capacitor)
C42  value 10uF  [C0805]  (hidden comment: Capacitor)
C43  value 4.7uF  [C0603]  (hidden comment: Capacitor)
C44  value 100nF  [C0603]  (hidden comment: Capacitor)
C45  value 4.7uF  [C0603]  (hidden comment: Capacitor)
HW4  value SNT-100-BK-G  (hidden comment: Shunt Black 2.54mm)  (mechanical)
HW13  value SNT-100-BK-G  (hidden comment: Shunt Black 2.54mm)  (mechanical)
JP2  value Shunt Fitted 1-2  [CON_SAMTEC_TSW-104-07-X-D]  (hidden comment: Jumper_Header 4x2 Fitted 1-2)
JP5  value Shunt Fitted 1-2  [CON_SAMTEC_TSW-103-07-F-S]  (hidden comment: Jumper_Header 3x1 Fitted 1-2)
LD5  value GREEN  [LED_0603_OSRAM_LG-Q396-PS-35_GREEN_1A2K_H0P4]  (hidden comment: LED_green)
R12  value 620R  [R0603]  (hidden comment: Resistor)
R25  value 10K  [R0402]  (hidden comment: Resistor)
R30  value 10K  [R0402]  (hidden comment: Resistor)
R31  value 27K  [R0402]  (hidden comment: Resistor)
R32  value 56K  [R0402]  (hidden comment: Resistor)
SB2  SB_ON  [SOLDER-BRIDGE_R0603-0R]  (value not drawn)
SB6  SB_ON  [SOLDER-BRIDGE_R0603-0R]  (value not drawn)
SB80  SB_ON  [SOLDER-BRIDGE_R0603-0R]  (value not drawn)
TP1  Test Point  [TP_SMD_1MM]  (value not drawn)  (no BOM)
TP2  Test Point  [TP_SMD_1MM]  (value not drawn)  (no BOM)
TP3  Test Point  [TP_SMD_1MM]  (value not drawn)  (no BOM)
U11  value ST1L05CPU33R 3.3V 1.3A  [ICC_DFN6-EPAD_3X3_P095]  (hidden comment: ST1L05CPU33R)
U12  LD1117S50TR  [REG_SOT223-TAB]
U13  ST1L05BPUR  [ICC_DFN6-EPAD_3X3_P095]

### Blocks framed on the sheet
3V3 PWR: C38-C40 R25 SB2 TP1 U11

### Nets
1V8: JP5.3 SB80.2
3V3: JP5.1 SB2.2 SB6.1 TP1.1
5V: C40.2 JP2.2 JP2.4 JP2.6 JP2.8 R12.2 R25.2 U11.6(VI)
5V_EXT: JP2.5
5V_USB_CHGR: JP2.7
5V_USB_STLK: JP2.1
5V_VIN: C41.2 JP2.3 U12.2(Vout) U12.4(Tab)
GND: C38.2 C39.1 C40.1 C41.1 C42.1 C43.1 C44.1 C45.1 LD5.2 R32.1 U11.2(GND) U11.EP(GND) U12.1(Gnd) U13.2(GND) U13.EP(GND)
VDD: JP5.2
VIN: C42.2 U12.3(Vin)
NetC38_1: C38.1 R25.1 U11.1(EN)
NetC39_2: C39.2 SB2.1 U11.4(VO) U11.5(VO_SENSE)
NetC43_2: C43.2 R30.2 SB6.2 U13.6(VI)
NetC44_2: C44.2 R30.1 U13.1(EN)
NetC45_2: C45.2 R31.2 SB80.1 TP2.1 U13.4(VO)
NetLD5_1: LD5.1 R12.1
NetR31_1: R31.1 R32.2 U13.5(ADJ)
NetTP3_1: TP3.1 U13.3(PG)

Not connected (* = marked no-connect by the designer): U11 3(NC)*

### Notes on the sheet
- VIN / 5V PWR
- 5V  PWR SELECTION
- 5V_VIN
- STLK
- VIN
- EXT
- (near R12) 5V
- 5V_EXT from Morpho connector
- CHGR
- 5V_USB_CHGR used as Charger mode
- 1V8 PWR
- Vout=1.22*(1+R1/R2)
- (near TP2) 1V8

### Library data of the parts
C38 = MCD-00006: Capacitor, MLCC, 100nF, 16V, X7R, 10%, 0402, T=0.5mm; Manufacturer_Part_Number: CC0402KRX7R7BB104; Manufacturer: YAGEO; Alternate_Manufacturer_Part_Number: GCM155R71C104KA55D; Alternate_Manufacturer: MURATA; Provided_By: SUBCO; ECCN_US: EAR99; ECCN_EU: NEC
C39 C45 = MCD-01121: Capacitor, MLCC, 4.7µF, 10V, X5R, 20%, 0603, T=0,8mm; Manufacturer_Part_Number: GRM188R61A475ME15; Manufacturer: MURATA; Provided_By: SUBCO; ECCN_US: EAR99; ECCN_EU: NEC
C40 C43 = MCD-00097: Capacitor, MLCC, 4.7uF, 16V, X5R, 20%, 0603, T=0,8mm; Manufacturer_Part_Number: GRM188R61C475KE11; Manufacturer: MURATA; Alternate_Manufacturer_Part_Number: GRM188R61C475MAAJ; Provided_By: SUBCO; ECCN_US: EAR99; ECCN_EU: NEC
C41 C42 = MCD-00014: Capacitor, MLCC, 10uF, 25V, X5R, 10%, 0805, T=0,85mm; Manufacturer_Part_Number: CC0805KRX5R8BB106; Manufacturer: YAGEO; Provided_By: SUBCO; ECCN_US: EAR99; ECCN_EU: NEC
C44 = MCD-00237: as C65 on sheet Connectors
HW4 HW13 = MCD-00043: as HW1 on sheet Connectors
JP2 = MCD-00686: Header, 4x2, 2,54mm, VR, TH, Height 5.84mm/2.54mm - Shunt Fitted 1-2; Part_Type: Connector; Manufacturer_Part_Number: TSW-104-07-x-D; Manufacturer: SAMTEC; Provided_By: SUBCO
JP5 = MCD-00684: Header, 3x1, 2,54mm, VR, TH, Height 5.84mm/2.54mm - Shunt Fitted 1-2 by default; Part_Type: Connector; Manufacturer_Part_Number: TSW-103-07-F-S; Manufacturer: SAMTEC; Provided_By: SUBCO
LD5 = MCD-00588: as LD1 on sheet Connectors
R12 = MCD-00500: Resistor,620R,0603,1%,1/10W; Manufacturer_Part_Number: RC0603FR-07620RL; Manufacturer: YAGEO; Provided_By: SUBCO; ECCN_US: EAR99; ECCN_EU: NEC
R25 R30 = MCD-00053: Resistor,10K,0402,1%,1/16W; Manufacturer_Part_Number: RC0402FR-0710KL; Manufacturer: YAGEO; Provided_By: SUBCO; ECCN_US: EAR99; ECCN_EU: NEC
R31 = MCD-00443: Resistor,27K,0402,1%,1/16W; Manufacturer_Part_Number: RC0402FR-0727KL; Manufacturer: YAGEO; Provided_By: SUBCO; ECCN_US: EAR99; ECCN_EU: NEC
R32 = MCD-00493: Resistor,56K,0402,1%,1/16W; Manufacturer_Part_Number: RC0402FR-0756KL; Manufacturer: YAGEO; Provided_By: SUBCO; ECCN_US: EAR99; ECCN_EU: NEC
SB2 SB6 SB80 = MCD-00071: as SB7 on sheet Connectors
TP1-TP3 = MCD-00074: Test Point 1mm; Part_Type: Mechanical
U11 = MCD-01025: LDO, 3.3V, 1.3A, Very low quiescent current BiCMOS voltage regulator; Part_Type: IC; Manufacturer: STMICROELECTRONICS; BMS_Part_Number: 9176246; Provided_By: SUBCO with ST control; ECCN_US: EAR99; ECCN_EU: NEC
U12 = MCD-00088: IC REG LDO 5V 0.8A SOT223; Manufacturer: STMICROELECTRONICS; BMS_Part_Number: 9176133; Provided_By: SUBCO with ST control; ECCN_US: EAR99; ECCN_EU: NEC
U13 = MCD-00581: LDO Linear Voltage Regulator IC Positive Adjustable 1 Output Adjustable 1.3A 6-DFN (3x3); Manufacturer: STMICROELECTRONICS; BMS_Part_Number: 9176239; Provided_By: SUBCO with ST control; ECCN_US: EAR99; ECCN_EU: NEC

## Sheet MCU_144_IOs.SchDoc: MCU 144 I/Os
size A3; Date: Not used; ApprovedBy: Not used; CheckedBy: Not used; Author: Not used; CompanyName: STMicroelectronics; DrawnBy: Not used; Engineer: Not used; Organization: Not used; Address1: Not used; Address2: Not used; Address3: Not used; Address4: Not used; DocumentNumber: 3; Revision: Not used; SheetNumber: 3; SheetTotal: 9
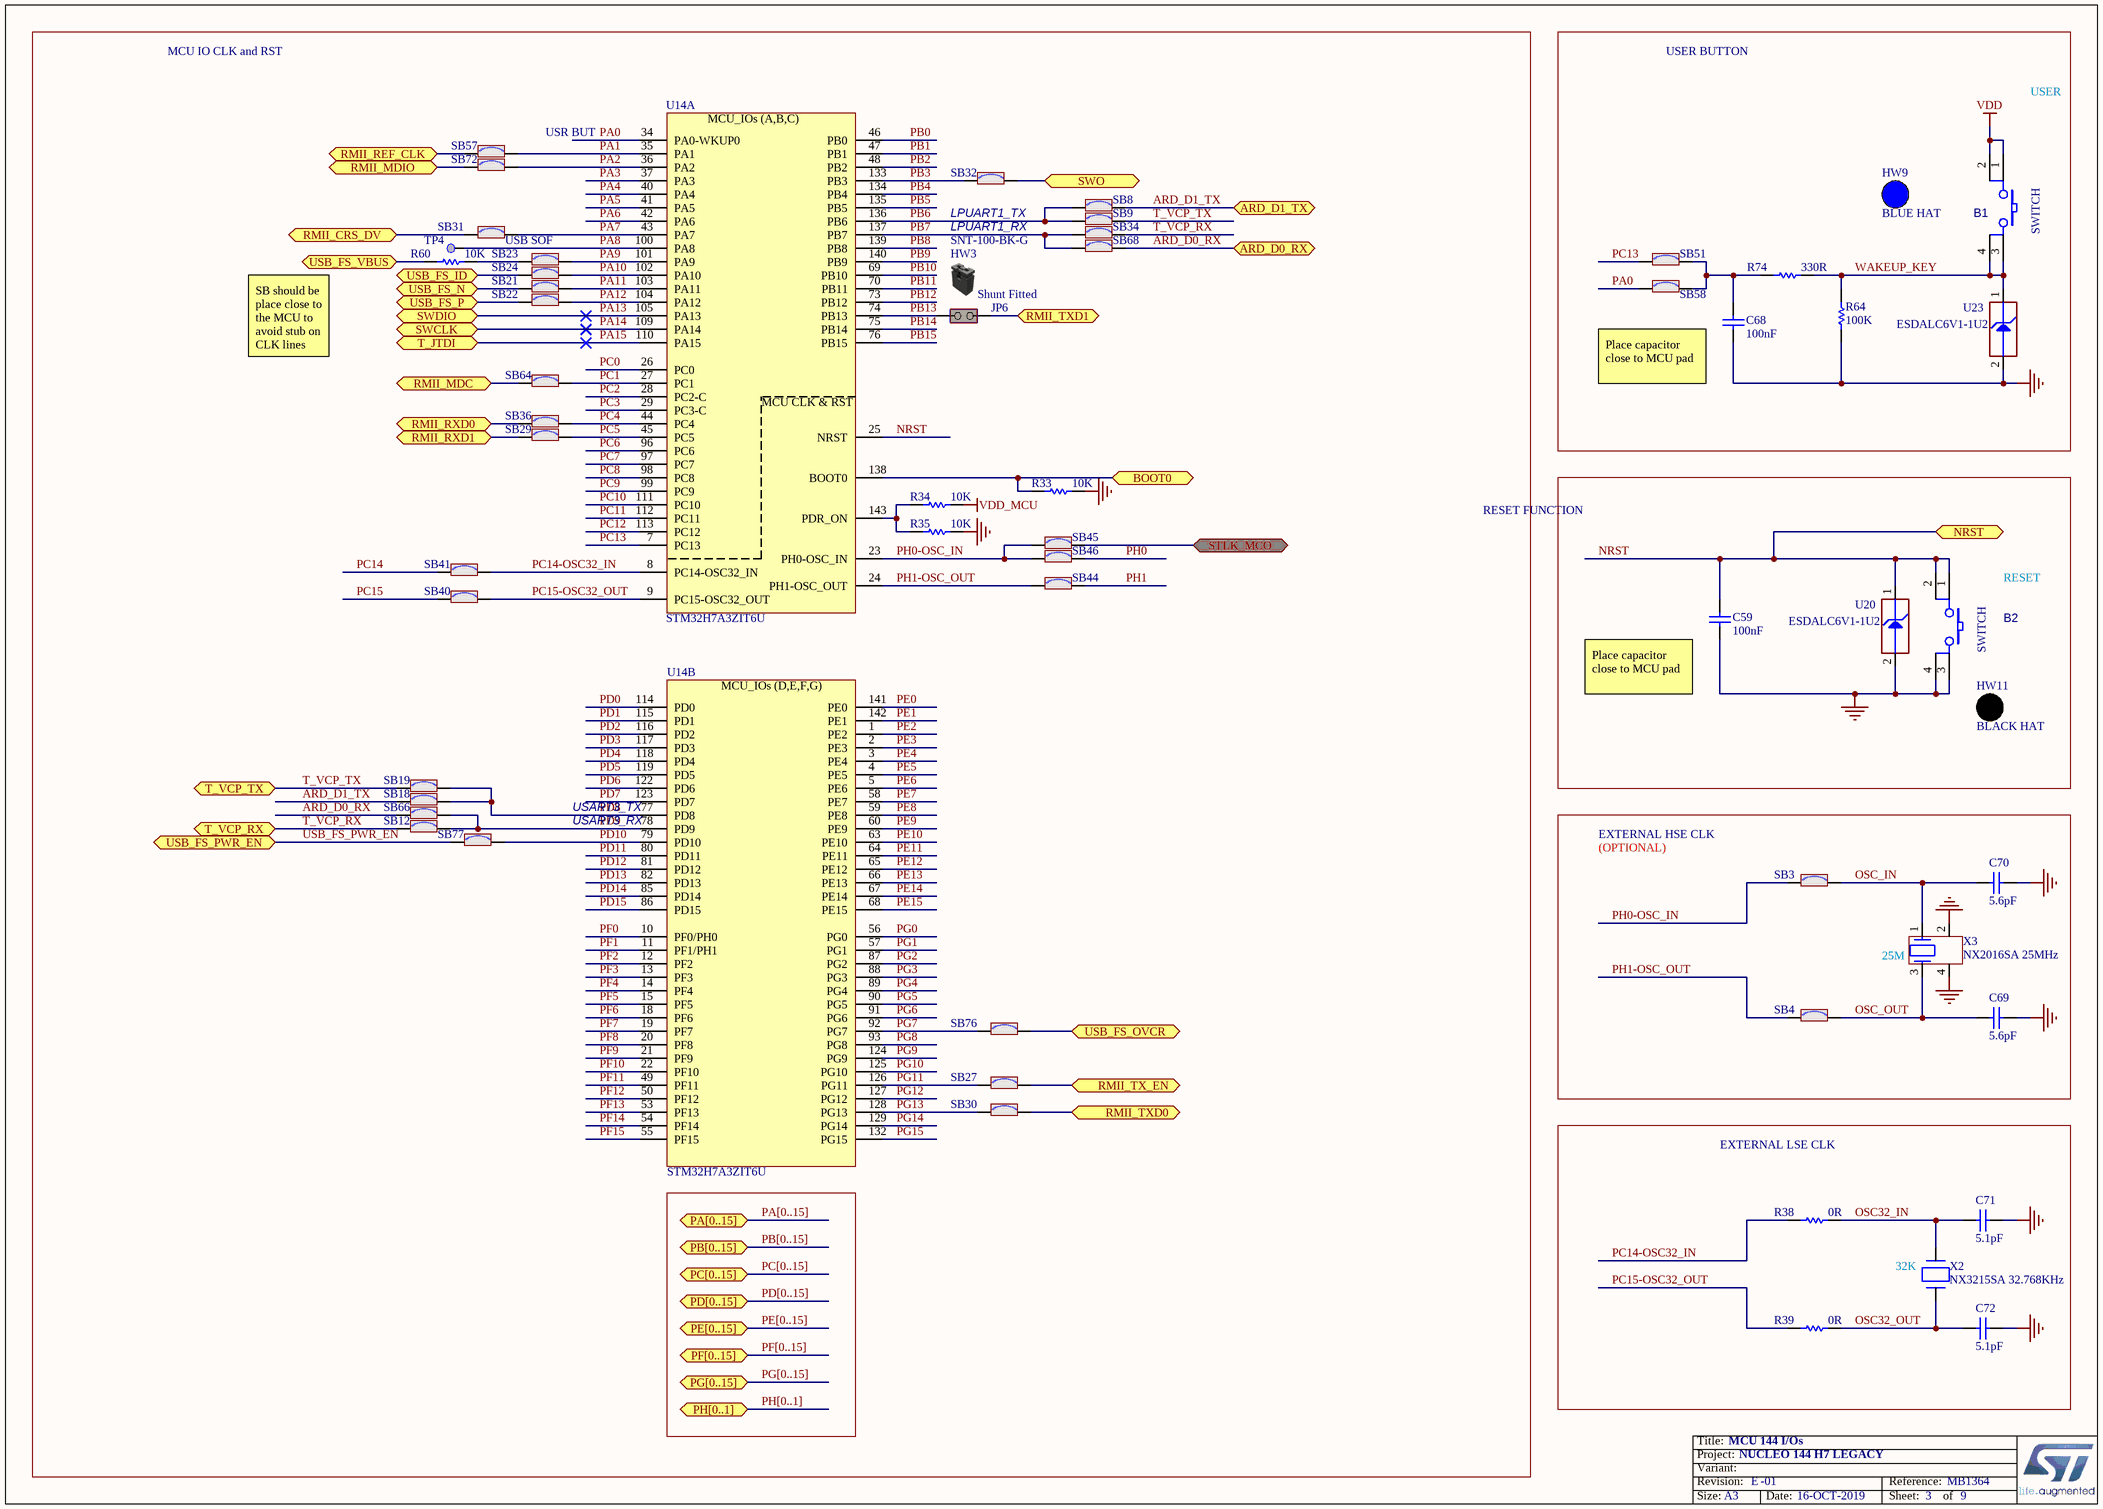
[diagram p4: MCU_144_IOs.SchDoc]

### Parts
B1  value SWITCH  [SWI_WEALTHMETAL_TD-0341_4P_BLUE]  (hidden comment: SW-PUSH-CMS)
B2  value SWITCH  [SWI_WEALTHMETAL_TD-0341_4P_BLACK]  (hidden comment: SW-PUSH-CMS)
C59  value 100nF  [C0603]  (hidden comment: Capacitor)
C68  value 100nF  [C0603]  (hidden comment: Capacitor)
C69  value 5.6pF  [C0402]  (hidden comment: Capacitor)
C70  value 5.6pF  [C0402]  (hidden comment: Capacitor)
C71  value 5.1pF  [C0402]  (hidden comment: Capacitor)
C72  value 5.1pF  [C0402]  (hidden comment: Capacitor)
HW3  value SNT-100-BK-G  (hidden comment: Shunt Black 2.54mm)  (mechanical)
HW9  value BLUE HAT  (hidden comment: BUTTON_HAT_BLUE)  (mechanical)
HW11  value BLACK HAT  (hidden comment: BUTTON_HAT_BLACK)  (mechanical)
JP6  value Shunt Fitted  [CON_SAMTEC_TSW-102-07-G-S]  (hidden comment: Jumper_Header 2x1 Fitted)
R33  value 10K  [R0603]  (hidden comment: Resistor)
R34  value 10K  [R0603]  (hidden comment: Resistor)
R35  value 10K  [R0603]  (hidden comment: Resistor)
R38  value 0R  [R0603]  (hidden comment: Resistor)
R39  value 0R  [R0603]  (hidden comment: Resistor)
R60  value 10K  [R0402]  (hidden comment: Resistor)
R64  value 100K  [R0603]  (hidden comment: Resistor)
R74  value 330R  [R0603]  (hidden comment: Resistor)
SB3  SB_ON  [SOLDER-BRIDGE_R0603-0R]  (value not drawn)
SB4  SB_ON  [SOLDER-BRIDGE_R0603-0R]  (value not drawn)
SB8  SB_ON  [SOLDER-BRIDGE_R0603-0R]  (value not drawn)
SB9  SB_ON  [SOLDER-BRIDGE_R0603-0R]  (value not drawn)
SB12  SB_ON  [SOLDER-BRIDGE_R0603-0R]  (value not drawn)
SB18  SB_ON  [SOLDER-BRIDGE_R0603-0R]  (value not drawn)
SB19  SB_ON  [SOLDER-BRIDGE_R0603-0R]  (value not drawn)
SB21  SB_ON  [SOLDER-BRIDGE_R0603-0R]  (value not drawn)
SB22  SB_ON  [SOLDER-BRIDGE_R0603-0R]  (value not drawn)
SB23  SB_ON  [SOLDER-BRIDGE_R0603-0R]  (value not drawn)
SB24  SB_ON  [SOLDER-BRIDGE_R0603-0R]  (value not drawn)
SB27  SB_ON  [SOLDER-BRIDGE_R0603-0R]  (value not drawn)
SB29  SB_ON  [SOLDER-BRIDGE_R0603-0R]  (value not drawn)
SB30  SB_ON  [SOLDER-BRIDGE_R0603-0R]  (value not drawn)
SB31  SB_ON  [SOLDER-BRIDGE_R0603-0R]  (value not drawn)
SB32  SB_ON  [SOLDER-BRIDGE_R0603-0R]  (value not drawn)
SB34  SB_ON  [SOLDER-BRIDGE_R0603-0R]  (value not drawn)
SB36  SB_ON  [SOLDER-BRIDGE_R0603-0R]  (value not drawn)
SB40  SB_ON  [SOLDER-BRIDGE_R0603-0R]  (value not drawn)
SB41  SB_ON  [SOLDER-BRIDGE_R0603-0R]  (value not drawn)
SB44  SB_ON  [SOLDER-BRIDGE_R0603-0R]  (value not drawn)
SB45  SB_ON  [SOLDER-BRIDGE_R0603-0R]  (value not drawn)
SB46  SB_ON  [SOLDER-BRIDGE_R0603-0R]  (value not drawn)
SB51  SB_ON  [SOLDER-BRIDGE_R0603-0R]  (value not drawn)
SB57  SB_ON  [SOLDER-BRIDGE_R0603-0R]  (value not drawn)
SB58  SB_ON  [SOLDER-BRIDGE_R0603-0R]  (value not drawn)
SB64  SB_ON  [SOLDER-BRIDGE_R0603-0R]  (value not drawn)
SB66  SB_ON  [SOLDER-BRIDGE_R0402-0R]  (value not drawn)
SB68  SB_ON  [SOLDER-BRIDGE_R0402-0R]  (value not drawn)
SB72  SB_ON  [SOLDER-BRIDGE_R0603-0R]  (value not drawn)
SB76  SB_ON  [SOLDER-BRIDGE_R0603-0R]  (value not drawn)
SB77  SB_ON  [SOLDER-BRIDGE_R0603-0R]  (value not drawn)
TP4  Test Point  [TP_SMD_1MM]  (value not drawn)  (no BOM)
U14  value STM32H7A3ZIT6U  [ICC_LQFP144_20X20_P050_SOCKET_YAMAICHI_IC149-144-145-B5_NM]  (hidden comment: STM32H7A3ZIT6)  (parts A,B of 3)
U20  value ESDALC6V1-1U2  [ESD_ST0201]  (hidden comment: ESD-TRANSIL)
U23  value ESDALC6V1-1U2  [ESD_ST0201]  (hidden comment: ESD-TRANSIL)
X2  value NX3215SA 32.768KHz  [CRY_NX3215SA_2P]  (hidden comment: XTAL_2_PINS)
X3  value NX2016SA 25MHz  [CRY_NX2016SA_4P]  (hidden comment: XTAL_4_PINS)

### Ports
ARD_D0_RX (bidir), ARD_D1_TX (bidir), BOOT0 (bidir), NRST (bidir), PA[0..15] (bidir), PB[0..15] (bidir), PC[0..15] (bidir), PD[0..15] (bidir), PE[0..15] (bidir), PF[0..15] (bidir), PG[0..15] (bidir), PH[0..1] (bidir), RMII_CRS_DV (bidir), RMII_MDC (bidir), RMII_MDIO (bidir), RMII_REF_CLK (bidir), RMII_RXD0 (bidir), RMII_RXD1 (bidir), RMII_TX_EN (bidir), RMII_TXD0 (bidir), RMII_TXD1 (bidir), STLK_MCO (bidir), SWCLK (bidir), SWDIO (bidir), SWO (bidir), T_JTDI (bidir), T_VCP_RX (bidir), T_VCP_TX (bidir), USB_FS_ID (bidir), USB_FS_N (bidir), USB_FS_OVCR, USB_FS_P (bidir), USB_FS_PWR_EN (bidir), USB_FS_VBUS (bidir)

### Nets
GND: B2.3 B2.4 C59.1 C68.1 C69.2 C70.2 C71.2 C72.2 R33.2 R35.2 R64.1 U20.2(GND) U23.2(GND) X3.2 X3.4
VDD: B1.1 B1.2
VDD_MCU: R34.2
ARD_D0_RX: SB66.1 SB68.2 ; port ARD_D0_RX
ARD_D1_TX: SB8.1 SB18.2 ; port ARD_D1_TX
BOOT0: R33.1 U14.138(BOOT0) ; port BOOT0
NRST: B2.1 B2.2 C59.2 U14.25(NRST) U20.1(IO1) ; port NRST
OSC32_IN: C71.1 R38.2 X2.2(X2)
OSC32_OUT: C72.1 R39.2 X2.1(X1)
OSC_IN: C70.1 SB3.2 X3.1
OSC_OUT: C69.1 SB4.2 X3.3
PA0: SB58.2 U14.34(PA0-WKUP0)
PA1: SB57.1 U14.35(PA1)
PA2: SB72.1 U14.36(PA2)
PA3: U14.37(PA3)
PA4: U14.40(PA4)
PA5: U14.41(PA5)
PA6: U14.42(PA6)
PA7: SB31.1 U14.43(PA7)
PA8: TP4.1 U14.100(PA8)
PA9: SB23.1 U14.101(PA9)
PA10: SB24.1 U14.102(PA10)
PA11: SB21.1 U14.103(PA11)
PA12: SB22.1 U14.104(PA12)
PA13: U14.105(PA13) ; port SWDIO
PA14: U14.109(PA14) ; port SWCLK
PA15: U14.110(PA15) ; port T_JTDI
PB0: U14.46(PB0)
PB1: U14.47(PB1)
PB2: U14.48(PB2)
PB3: SB32.2 U14.133(PB3)
PB4: U14.134(PB4)
PB5: U14.135(PB5)
PB6: SB8.2 SB9.2 U14.136(PB6)
PB7: SB34.2 SB68.1 U14.137(PB7)
PB8: U14.139(PB8)
PB9: U14.140(PB9)
PB10: U14.69(PB10)
PB11: U14.70(PB11)
PB12: U14.73(PB12)
PB13: JP6.1(COMMON) U14.74(PB13)
PB14: U14.75(PB14)
PB15: U14.76(PB15)
PC0: U14.26(PC0)
PC1: SB64.2 U14.27(PC1)
PC2: U14.28(PC2-C)
PC3: U14.29(PC3-C)
PC4: SB36.2 U14.44(PC4)
PC5: SB29.2 U14.45(PC5)
PC6: U14.96(PC6)
PC7: U14.97(PC7)
PC8: U14.98(PC8)
PC9: U14.99(PC9)
PC10: U14.111(PC10)
PC11: U14.112(PC11)
PC12: U14.113(PC12)
PC13: SB51.2 U14.7(PC13)
PC14: SB41.1
PC14-OSC32_IN: R38.1 SB41.2 U14.8(PC14-OSC32_IN)
PC15: SB40.1
PC15-OSC32_OUT: R39.1 SB40.2 U14.9(PC15-OSC32_OUT)
PD0: U14.114(PD0)
PD1: U14.115(PD1)
PD2: U14.116(PD2)
PD3: U14.117(PD3)
PD4: U14.118(PD4)
PD5: U14.119(PD5)
PD6: U14.122(PD6)
PD7: U14.123(PD7)
PD8: SB18.1 SB19.1 U14.77(PD8)
PD9: SB12.1 SB66.2 U14.78(PD9)
PD10: SB77.1 U14.79(PD10)
PD11: U14.80(PD11)
PD12: U14.81(PD12)
PD13: U14.82(PD13)
PD14: U14.85(PD14)
PD15: U14.86(PD15)
PE0: U14.141(PE0)
PE1: U14.142(PE1)
PE2: U14.1(PE2)
PE3: U14.2(PE3)
PE4: U14.3(PE4)
PE5: U14.4(PE5)
PE6: U14.5(PE6)
PE7: U14.58(PE7)
PE8: U14.59(PE8)
PE9: U14.60(PE9)
PE10: U14.63(PE10)
PE11: U14.64(PE11)
PE12: U14.65(PE12)
PE13: U14.66(PE13)
PE14: U14.67(PE14)
PE15: U14.68(PE15)
PF0: U14.10(PF0/PH0)
PF1: U14.11(PF1/PH1)
PF2: U14.12(PF2)
PF3: U14.13(PF3)
PF4: U14.14(PF4)
PF5: U14.15(PF5)
PF6: U14.18(PF6)
PF7: U14.19(PF7)
PF8: U14.20(PF8)
PF9: U14.21(PF9)
PF10: U14.22(PF10)
PF11: U14.49(PF11)
PF12: U14.50(PF12)
PF13: U14.53(PF13)
PF14: U14.54(PF14)
PF15: U14.55(PF15)
PG0: U14.56(PG0)
PG1: U14.57(PG1)
PG2: U14.87(PG2)
PG3: U14.88(PG3)
PG4: U14.89(PG4)
PG5: U14.90(PG5)
PG6: U14.91(PG6)
PG7: SB76.2 U14.92(PG7)
PG8: U14.93(PG8)
PG9: U14.124(PG9)
PG10: U14.125(PG10)
PG11: SB27.2 U14.126(PG11)
PG12: U14.127(PG12)
PG13: SB30.2 U14.128(PG13)
PG14: U14.129(PG14)
PG15: U14.132(PG15)
PH0: SB46.2
PH0-OSC_IN: SB3.1 SB45.1 SB46.1 U14.23(PH0-OSC_IN)
PH1: SB44.2
PH1-OSC_OUT: SB4.1 SB44.1 U14.24(PH1-OSC_OUT)
RMII_CRS_DV: SB31.2 ; port RMII_CRS_DV
RMII_MDC: SB64.1 ; port RMII_MDC
RMII_MDIO: SB72.2 ; port RMII_MDIO
RMII_REF_CLK: SB57.2 ; port RMII_REF_CLK
RMII_RXD0: SB36.1 ; port RMII_RXD0
RMII_RXD1: SB29.1 ; port RMII_RXD1
RMII_TX_EN: SB27.1 ; port RMII_TX_EN
RMII_TXD0: SB30.1 ; port RMII_TXD0
RMII_TXD1: JP6.2(NO) ; port RMII_TXD1
STLK_MCO: SB45.2 ; port STLK_MCO
SWO: SB32.1 ; port SWO
T_VCP_RX: SB12.2 SB34.1 ; port T_VCP_RX
T_VCP_TX: SB9.1 SB19.2 ; port T_VCP_TX
USB_FS_ID: SB24.2 ; port USB_FS_ID
USB_FS_N: SB21.2 ; port USB_FS_N
USB_FS_OVCR: SB76.1 ; port USB_FS_OVCR
USB_FS_P: SB22.2 ; port USB_FS_P
USB_FS_PWR_EN: SB77.2 ; port USB_FS_PWR_EN
USB_FS_VBUS: R60.1 ; port USB_FS_VBUS
WAKEUP_KEY: B1.3 B1.4 R64.2 R74.2 U23.1(IO1)
NetC68_2: C68.2 R74.1 SB51.1 SB58.1
NetR34_1: R34.1 R35.1 U14.143(PDR_ON)
NetR60_2: R60.2 SB23.2

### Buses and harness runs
bus PA[0..15] = port PA[0..15]
bus PB[0..15] = port PB[0..15]
bus PC[0..15] = port PC[0..15]
bus PD[0..15] = port PD[0..15]
bus PE[0..15] = port PE[0..15]
bus PF[0..15] = port PF[0..15]
bus PG[0..15] = port PG[0..15]
bus PH[0..1] = port PH[0..1]

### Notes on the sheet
- MCU IO CLK and RST
- USER BUTTON
- USER
- USR BUT
- (near SB31) USB SOF
- LPUART1_TX
- LPUART1_RX
- SB should be place close to the MCU to avoid stub on CLK lines
- Place capacitor close to MCU pad
- RESET FUNCTION
- RESET
- (near C59) Place capacitor close to MCU pad
- (near SB77) USART3_TX
- (near SB77) USART3_RX
- EXTERNAL HSE CLK
- (OPTIONAL)
- (near X3) 25M
- EXTERNAL LSE CLK
- (near X2) 32K

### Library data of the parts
B1 = MCD-00002: Non-Open Push-Button 0.1A 24V; Manufacturer_Part_Number: TD-0341; Manufacturer: WEALTHMETAL; Part_Type: Misc; Provided_By: SUBCO
B2 = MCD-00001: Non-Open Push-Button 0.1A 24V BLACK; Manufacturer_Part_Number: TD-0341; Manufacturer: WEALTHMETAL; Part_Type: Misc; Provided_By: SUBCO
C59 C68 = MCD-00237: as C65 on sheet Connectors
C69 C70 = MCD-01374: Capacitor, MLCC, 5.6pF, 50V, NPO, 5%, 0402, T=0,5mm; Manufacturer_Part_Number: CC0402BRNPO9BN5R6; Manufacturer: YAGEO; Provided_By: SUBCO
C71 C72 = MCD-00003: Capacitor, MLCC, 5.1pF, 50V, NPO, +-0.25pF, 0402, T=0.5mm; Manufacturer_Part_Number: CC0402CRNPO9BN5R1; Manufacturer: YAGEO; Provided_By: SUBCO; ECCN_US: EAR99; ECCN_EU: NEC
HW3 = MCD-00043: as HW1 on sheet Connectors
HW9 = MCD-00634: Blue Hat for switch TD0341X-G01-BLU; Part_Type: Mechanical; Manufacturer_Part_Number: 988.16.09.3.00002_SH-517; Manufacturer: JIUBABA; Provided_By: SUBCO
HW11 = MCD-00635: Black Hat for switch TD0341X-G01-BLA; Part_Type: Mechanical; Manufacturer_Part_Number: 988.16.09.3.00003_SH-517; Manufacturer: JIUBABA; Provided_By: SUBCO
JP6 = MCD-00683: Header, 2x1, 2,54mm, VR, TH, Height 5.84mm/2.54mm - Shunt Fitted by default; Part_Type: Connector; Manufacturer_Part_Number: TSW-102-07-x-S; Manufacturer: SAMTEC; Alternate_Manufacturer_Part_Number: 313102S111116; Alternate_Manufacturer: LIANYI; Provided_By: SUBCO
R33-R35 = MCD-00220: Resistor,10K,0603,1%,1/10W; Manufacturer_Part_Number: RC0603FR-0710KL; Manufacturer: YAGEO; Provided_By: SUBCO; ECCN_US: EAR99; ECCN_EU: NEC
R38 R39 = MCD-00056: Resistor,0R,0603,5%,1/10W; Manufacturer_Part_Number: RC0603JR-070RL; Manufacturer: YAGEO; Provided_By: SUBCO; ECCN_US: EAR99; ECCN_EU: NEC
R60 = MCD-00053: as R25 on sheet Power_Board
R64 = MCD-00223: as R68 on sheet Connectors
R74 = MCD-00197: Resistor,330R,0603,1%,1/10W; Manufacturer_Part_Number: RC0603FR-07330RL; Manufacturer: YAGEO; BMS_Part_Number: 9129729; Provided_By: SUBCO; ECCN_US: EAR99; ECCN_EU: NEC
SB3 SB4 SB8 SB9 SB12 SB18 SB19 SB21-SB24 SB27 SB29-SB32 SB34 SB36 SB40 SB41 SB44-SB46 SB51 SB57 SB58 SB64 SB72 SB76 SB77 = MCD-00071: as SB7 on sheet Connectors
SB66 SB68 = MCD-01618: as SB28 on sheet Connectors
TP4 = MCD-00074: Test Point 1mm; Part_Type: Mechanical
U14 = MCD-01349: STM32H7A3ZIT6U, LQFP144 package, 20x20; Part_Type: IC; Manufacturer: STMICROELECTRONICS; BMS_Part_Number: 9175347; Provided_By: SUBCO with ST control; ECCN_US: 3A991A2; ECCN_EU: NEC
U20 U23 = MCD-00170: ESD protection 6V1; Part_Type: Diode; Manufacturer: STMICROELECTRONICS; BMS_Part_Number: 9151132; Provided_By: SUBCO with ST control; ECCN_US: EAR99; ECCN_EU: NEC
X2 = MCD-00091: Crystal 32.768kHz, 6pF, +-20ppm, 50Kohms max, SMD; Manufacturer_Part_Number: NX3215SA 32.768KHz EXS00A-MU00525; Manufacturer: NDK; Part_Type: Crystal_Osc; BMS_Part_Number: 9157034; Provided_By: SUBCO; ECCN_US: EAR99; ECCN_EU: NEC
X3 = MCD-01364: Crystal 25MHz, 6pF, +-20ppm, 80ohms max, SMD; Part_Type: Crystal_Osc; Manufacturer_Part_Number: NX2016SA 25MHz EXS00A-CS11321; Manufacturer: NDK; BMS_Part_Number: 9157044; Provided_By: SUBCO; ECCN_US: EAR99; ECCN_EU: NEC

## Sheet MCU_144_POWER.SchDoc: MCU 144 POWER
size A4; Date: Not used; ApprovedBy: Not used; CheckedBy: Not used; Author: Not used; CompanyName: STMicroelectronics; DrawnBy: Not used; Engineer: Not used; Organization: Not used; Address1: Not used; Address2: Not used; Address3: Not used; Address4: Not used; DocumentNumber: 4; Revision: Not used; SheetNumber: 4; SheetTotal: 9
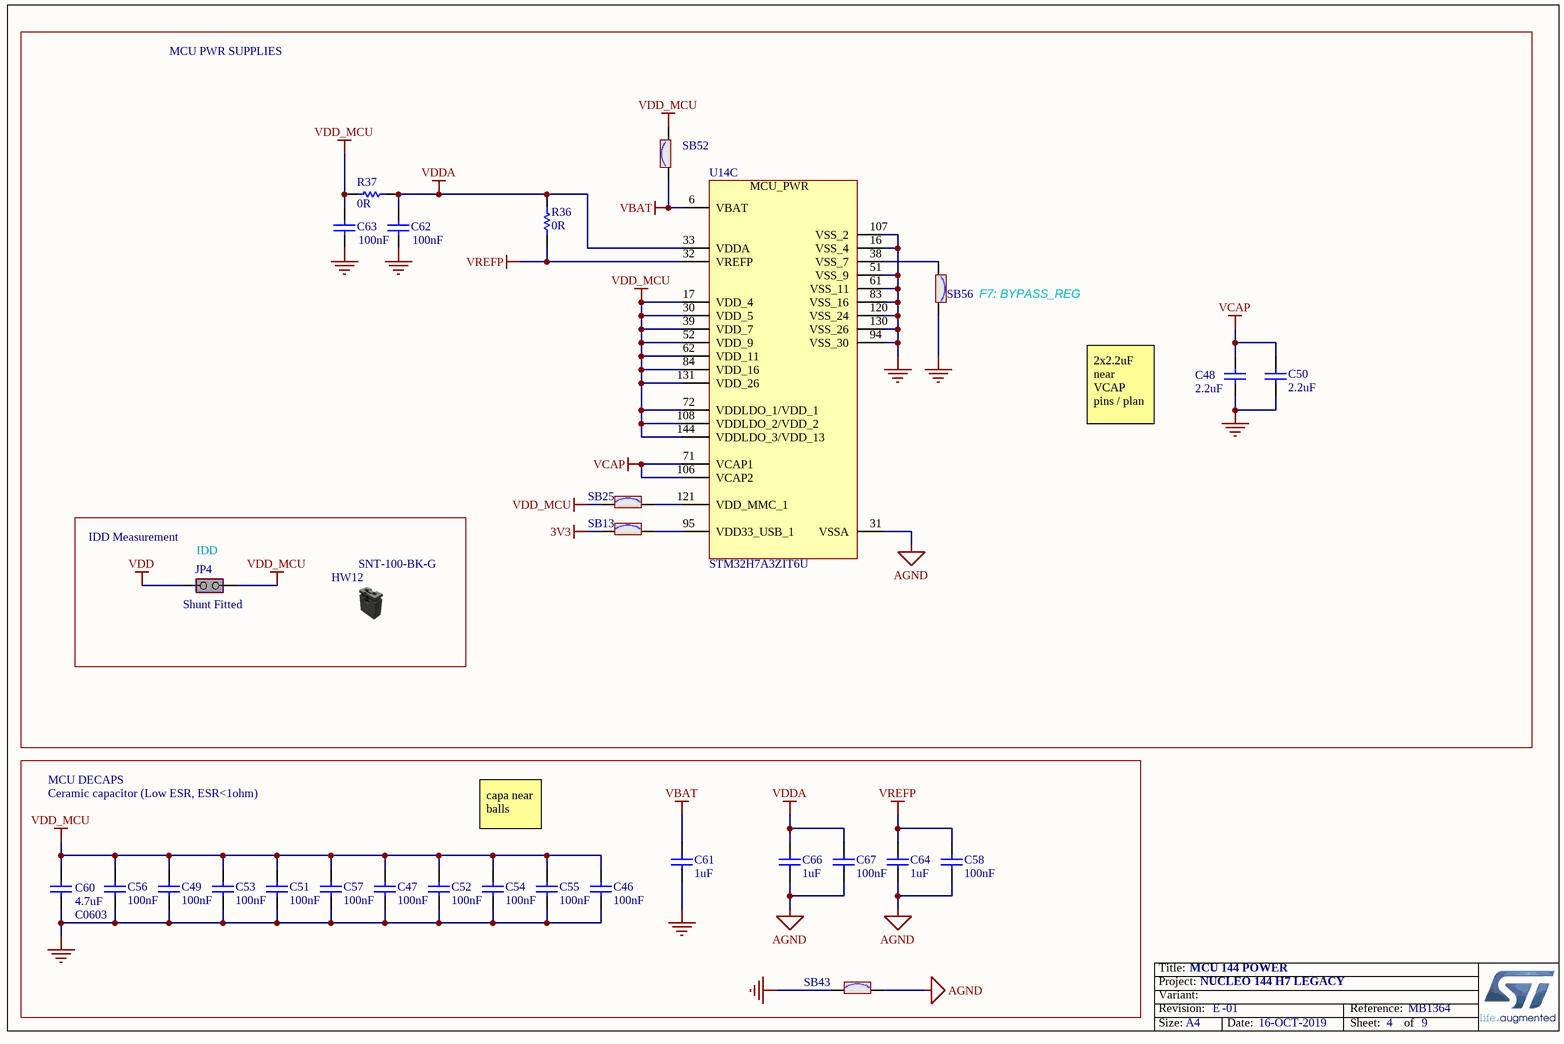
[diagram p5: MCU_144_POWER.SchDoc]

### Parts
C46  value 100nF  [C0402]  (hidden comment: Capacitor)
C47  value 100nF  [C0402]  (hidden comment: Capacitor)
C48  value 2.2uF  [C0603]  (hidden comment: Capacitor)
C49  value 100nF  [C0402]  (hidden comment: Capacitor)
C50  value 2.2uF  [C0603]  (hidden comment: Capacitor)
C51  value 100nF  [C0402]  (hidden comment: Capacitor)
C52  value 100nF  [C0402]  (hidden comment: Capacitor)
C53  value 100nF  [C0402]  (hidden comment: Capacitor)
C54  value 100nF  [C0402]  (hidden comment: Capacitor)
C55  value 100nF  [C0402]  (hidden comment: Capacitor)
C56  value 100nF  [C0402]  (hidden comment: Capacitor)
C57  value 100nF  [C0402]  (hidden comment: Capacitor)
C58  value 100nF  [C0402]  (hidden comment: Capacitor)
C60  value 4.7uF  [C0603]  (hidden comment: Capacitor)
C61  value 1uF  [C0603]  (hidden comment: Capacitor)
C62  value 100nF  [C0402]  (hidden comment: Capacitor)
C63  value 100nF  [C0402]  (hidden comment: Capacitor)
C64  value 1uF  [C0603]  (hidden comment: Capacitor)
C66  value 1uF  [C0603]  (hidden comment: Capacitor)
C67  value 100nF  [C0402]  (hidden comment: Capacitor)
HW12  value SNT-100-BK-G  (hidden comment: Shunt Black 2.54mm)  (mechanical)
JP4  value Shunt Fitted  [CON_SAMTEC_TSW-102-07-G-S]  (hidden comment: Jumper_Header 2x1 Fitted)
R36  value 0R  [R0603]  (hidden comment: Resistor)
R37  value 0R  [R0603]  (hidden comment: Resistor)
SB13  SB_ON  [SOLDER-BRIDGE_R0603-0R]  (value not drawn)
SB25  SB_ON  [SOLDER-BRIDGE_R0603-0R]  (value not drawn)
SB43  SB_ON  [SOLDER-BRIDGE_R0603-0R]  (value not drawn)
SB52  SB_ON  [SOLDER-BRIDGE_R0603-0R]  (value not drawn)
SB56  SB_ON  [SOLDER-BRIDGE_R0603-0R]  (value not drawn)
U14  value STM32H7A3ZIT6U  [ICC_LQFP144_20X20_P050_SOCKET_YAMAICHI_IC149-144-145-B5_NM]  (hidden comment: STM32H7A3ZIT6)  (part C of 3)

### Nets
3V3: SB13.1
AGND: C58.1 C64.2 C66.2 C67.1 SB43.2 U14.31(VSSA)
GND: C46.1 C47.1 C48.1 C49.1 C50.1 C51.1 C52.1 C53.1 C54.1 C55.1 C56.1 C57.1 C60.1 C61.1 C62.2 C63.2 SB43.1 SB56.2 U14.16(VSS_4) U14.51(VSS_9) U14.61(VSS_11) U14.83(VSS_16) U14.94(VSS_30) U14.107(VSS_2) U14.120(VSS_24) U14.130(VSS_26)
VBAT: C61.2 SB52.1 U14.6(VBAT)
VCAP: C48.2 C50.2 U14.71(VCAP1) U14.106(VCAP2)
VDD: JP4.1(COMMON)
VDD_MCU: C46.2 C47.2 C49.2 C51.2 C52.2 C53.2 C54.2 C55.2 C56.2 C57.2 C60.2 C63.1 JP4.2(NO) R37.1 SB25.1 SB52.2 U14.17(VDD_4) U14.30(VDD_5) U14.39(VDD_7) U14.52(VDD_9) U14.62(VDD_11) U14.72(VDDLDO_1/VDD_1) U14.84(VDD_16) U14.108(VDDLDO_2/VDD_2) U14.131(VDD_26) U14.144(VDDLDO_3/VDD_13)
VDDA: C62.1 C66.1 C67.2 R36.1 R37.2 U14.33(VDDA)
VREFP: C58.2 C64.1 R36.2 U14.32(VREFP)
NetSB13_2: SB13.2 U14.95(VDD33_USB_1)
NetSB25_2: SB25.2 U14.121(VDD_MMC_1)
NetSB56_1: SB56.1 U14.38(VSS_7)

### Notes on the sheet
- MCU PWR SUPPLIES
- (near SB56) F7: BYPASS_REG
- 2x2.2uF near VCAP pins / plan
- (near JP4) IDD Measurement
- (near JP4) IDD
- MCU DECAPS
- Ceramic capacitor (Low ESR, ESR<1ohm)
- capa near balls

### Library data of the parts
C46 C47 C49 C51-C58 C67 = MCD-01123: [obsolete] Capacitor, MLCC,100nF, 10V, X7R, 10%, 0402, T=0.5mm; Manufacturer_Part_Number: NRND_GRM155R71A104KA01; Manufacturer: MURATA; Provided_By: SUBCO; ECCN_US: EAR99; ECCN_EU: NEC
C48 C50 = MCD-00012: Capacitor, MLCC, 2.2uF, 10V, X5R, 10%, 0603, T=0,8mm; Manufacturer_Part_Number: CC0603KRX5R6BB225; Manufacturer: YAGEO; Alternate_Manufacturer_Part_Number: C0603C225K8PACTU; Alternate_Manufacturer: KEMET; Provided_By: SUBCO; ECCN_US: EAR99; ECCN_EU: NEC
C60 = MCD-01121: as C39 on sheet Power_Board
C61 C64 C66 = MCD-00238: Capacitor, MLCC, 1uF, 6V3, X5R, 10%, 0603, T=0,8mm; Manufacturer_Part_Number: CC0603KRX5R5BB105; Manufacturer: YAGEO; Provided_By: SUBCO; ECCN_US: EAR99; ECCN_EU: NEC
C62 C63 = MCD-00006: as C38 on sheet Power_Board
HW12 = MCD-00043: as HW1 on sheet Connectors
JP4 = MCD-00683: as JP6 on sheet MCU_144_IOs
R36 R37 = MCD-00056: as R38 on sheet MCU_144_IOs
SB13 SB25 SB43 SB52 SB56 = MCD-00071: as SB7 on sheet Connectors
U14 = MCD-01349: as U14 on sheet MCU_144_IOs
